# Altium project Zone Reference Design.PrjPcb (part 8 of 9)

## Sheet AM263P OSPI Bootmode.SchDoc
size 431 x 279 mm; Date: Not shown in title block; ApprovedBy: Not shown in title block; CheckedBy: Not shown in title block; Author: Not shown in title block; CompanyName: Not shown in title block; Engineer: Not shown in title block; Organization: Not shown in title block; Address1: Not shown in title block; Address2: Not shown in title block; Address3: Not shown in title block; Address4: Not shown in title block; DocumentNumber: 2; Revision: Use project parameter SCH_Rev; SheetNumber: 9; SheetTotal: 30; PageSetup: Record=PageOptions¦CenterHorizontal=True¦CenterVertical=True¦PrintScale=1.00¦XCorrection=1.00¦YCorrection=1.00¦PrintKind=0¦BorderSize=5000000¦LeftOffset=0¦BottomOffset=0¦Orientation=2¦PaperLength=1000¦PaperWidth=1000¦Scale=100¦PaperSource=15¦PrintQuality=600¦MediaType=1¦DitherType=10¦PaperKind=Letter¦PrintScaleMode=1
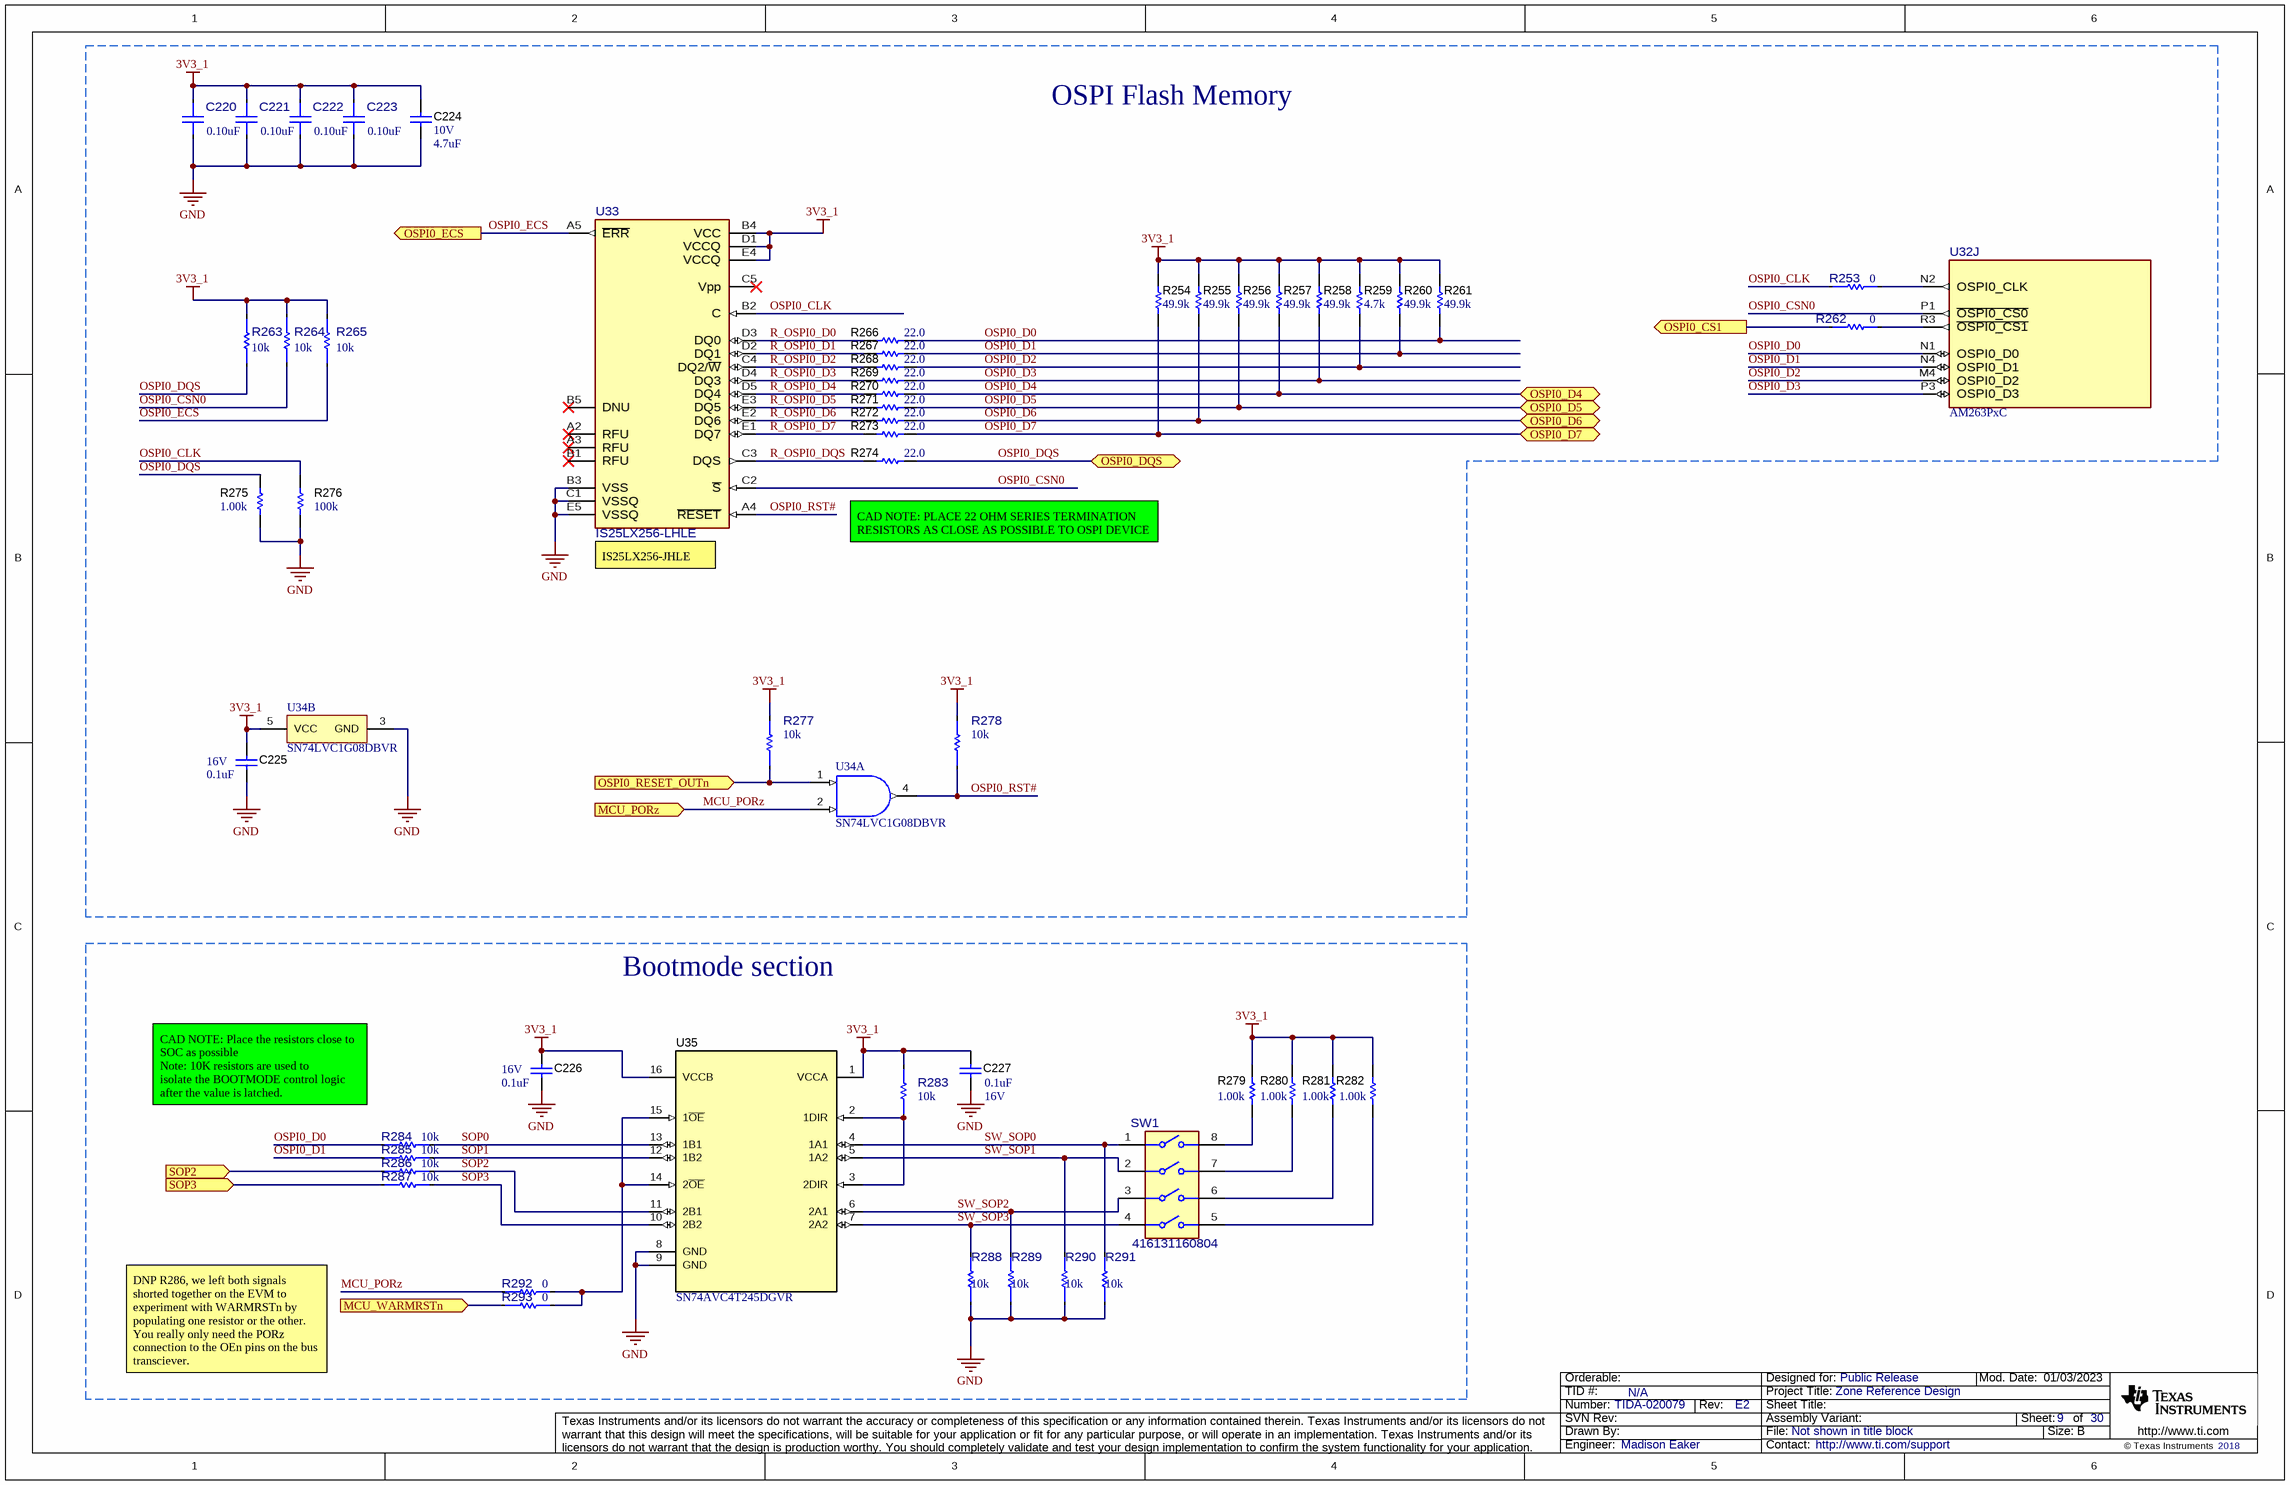
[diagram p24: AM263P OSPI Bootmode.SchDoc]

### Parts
C220  ValueDisplayed: 0.10uF  [FP-GRM155R71H104KE14D_0402-MFG]  (hidden comment: GRM155R71H104KE14D)
C221  ValueDisplayed: 0.10uF  [FP-GRM155R71H104KE14D_0402-MFG]  (hidden comment: GRM155R71H104KE14D)
C222  ValueDisplayed: 0.10uF  [FP-GRM155R71H104KE14D_0402-MFG]  (hidden comment: GRM155R71H104KE14D)
C223  ValueDisplayed: 0.10uF  [FP-GRM155R71H104KE14D_0402-MFG]  (hidden comment: GRM155R71H104KE14D)
C224  VDC_V: 10V  ValueDisplayed: 4.7uF  [0402]  (hidden comment: GRM155R61A475MEAAD)
C225  VDC_V: 16V  ValueDisplayed: 0.1uF  [0201]  (hidden comment: GRM033Z71C104KE14D)
C226  VDC_V: 16V  ValueDisplayed: 0.1uF  [0201]  (hidden comment: GRM033Z71C104KE14D)
C227  VDC_V: 16V  ValueDisplayed: 0.1uF  [0201]  (hidden comment: GRM033Z71C104KE14D)
R253  value 0  [FP-ERJ-2GE0R00X_0402-MFG]  (hidden comment: ERJ-2GE0R00X)
R254  ValueDisplayed: 49.9k  [0201]  (hidden comment: RC0201FR-0749K9L)
R255  ValueDisplayed: 49.9k  [0201]  (hidden comment: RC0201FR-0749K9L)
R256  ValueDisplayed: 49.9k  [0201]  (hidden comment: RC0201FR-0749K9L)
R257  ValueDisplayed: 49.9k  [0201]  (hidden comment: RC0201FR-0749K9L)
R258  ValueDisplayed: 49.9k  [0201]  (hidden comment: RC0201FR-0749K9L)
R259  ValueDisplayed: 4.7k  [0402]  (hidden comment: CRCW04024K70JNED)
R260  ValueDisplayed: 49.9k  [0201]  (hidden comment: RC0201FR-0749K9L)
R261  ValueDisplayed: 49.9k  [0201]  (hidden comment: RC0201FR-0749K9L)
R262  value 0  [FP-ERJ-2GE0R00X_0402-MFG]  (hidden comment: ERJ-2GE0R00X)
R263  value 10k  [FP-RC0402JR-0710KL_0402-MFG]  (hidden comment: RC0402JR-0710KL)
R264  value 10k  [FP-RC0402JR-0710KL_0402-MFG]  (hidden comment: RC0402JR-0710KL)
R265  value 10k  [FP-RC0402JR-0710KL_0402-MFG]  (hidden comment: RC0402JR-0710KL)
R266  ValueDisplayed: 22.0  [0201]  (hidden comment: RC0201FR-0722RL)
R267  ValueDisplayed: 22.0  [0201]  (hidden comment: RC0201FR-0722RL)
R268  ValueDisplayed: 22.0  [0201]  (hidden comment: RC0201FR-0722RL)
R269  ValueDisplayed: 22.0  [0201]  (hidden comment: RC0201FR-0722RL)
R270  ValueDisplayed: 22.0  [0201]  (hidden comment: RC0201FR-0722RL)
R271  ValueDisplayed: 22.0  [0201]  (hidden comment: RC0201FR-0722RL)
R272  ValueDisplayed: 22.0  [0201]  (hidden comment: RC0201FR-0722RL)
R273  ValueDisplayed: 22.0  [0201]  (hidden comment: RC0201FR-0722RL)
R274  ValueDisplayed: 22.0  [0201]  (hidden comment: RC0201FR-0722RL)
R275  ValueDisplayed: 1.00k  [0402]  (hidden comment: ERJ-2RKF1001X)
R276  ValueDisplayed: 100k  [0402]  (hidden comment: CRCW0402100KJNED)
R277  value 10k  [FP-RC0402JR-0710KL_0402-MFG]  (hidden comment: RC0402JR-0710KL)
R278  value 10k  [FP-RC0402JR-0710KL_0402-MFG]  (hidden comment: RC0402JR-0710KL)
R279  ValueDisplayed: 1.00k  [0402]  (hidden comment: ERJ-2RKF1001X)
R280  ValueDisplayed: 1.00k  [0402]  (hidden comment: ERJ-2RKF1001X)
R281  ValueDisplayed: 1.00k  [0402]  (hidden comment: ERJ-2RKF1001X)
R282  ValueDisplayed: 1.00k  [0402]  (hidden comment: ERJ-2RKF1001X)
R283  value 10k  [FP-RC0402JR-0710KL_0402-MFG]  (hidden comment: RC0402JR-0710KL)
R284  value 10k  [FP-RC0402JR-0710KL_0402-MFG]  (hidden comment: RC0402JR-0710KL)
R285  value 10k  [FP-RC0402JR-0710KL_0402-MFG]  (hidden comment: RC0402JR-0710KL)
R286  value 10k  [FP-RC0402JR-0710KL_0402-MFG]  (hidden comment: RC0402JR-0710KL)
R287  value 10k  [FP-RC0402JR-0710KL_0402-MFG]  (hidden comment: RC0402JR-0710KL)
R288  value 10k  [FP-RC0402JR-0710KL_0402-MFG]  (hidden comment: RC0402JR-0710KL)
R289  value 10k  [FP-RC0402JR-0710KL_0402-MFG]  (hidden comment: RC0402JR-0710KL)
R290  value 10k  [FP-RC0402JR-0710KL_0402-MFG]  (hidden comment: RC0402JR-0710KL)
R291  value 10k  [FP-RC0402JR-0710KL_0402-MFG]  (hidden comment: RC0402JR-0710KL)
R292  value 0  [FP-ERJ-2GE0R00X_0402-MFG]  (hidden comment: ERJ-2GE0R00X)
R293  value 0  [FP-ERJ-2GE0R00X_0402-MFG]  (hidden comment: ERJ-2GE0R00X)
SW1  416131160804  [FP-416131160804_SMT_SW-MFG]
U32  AM263PxC  [ZCZ0324A-MFG]  (part J of 13)
U33  IS25LX256-LHLE  [FP-IS25LX256-LHLE_TFBGA24-IPC_C]
U34  SN74LVC1G08DBVR  [DBV0005A_N]  (parts A,B of 2)
U35  SN74AVC4T245DGVR  [DGV0016A_N]

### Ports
MCU_PORz (in), MCU_WARMRSTn (in), OSPI0_CS1 (out), OSPI0_D4 (bidir), OSPI0_D5 (bidir), OSPI0_D6 (bidir), OSPI0_D7 (bidir), OSPI0_DQS (bidir), OSPI0_ECS (out), OSPI0_RESET_OUTn (in), SOP2 (in), SOP3 (in)

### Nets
3V3_1: C220.1 C221.1 C222.1 C223.1 C224.2 C225.1 C226.1 C227.1 R254.2 R255.2 R256.2 R257.2 R258.2 R259.2 R260.2 R261.2 R263.2 R264.1 R265.2 R277.2 R278.2 R279.2 R280.2 R281.2 R282.2 R283.2 U33.B4(VCC) U33.D1(VCCQ) U33.E4(VCCQ) U34.5(VCC) U35.1(VCCA) U35.16(VCCB)
GND: C220.2 C221.2 C222.2 C223.2 C224.1 C225.2 C226.2 C227.2 R275.1 R276.1 R288.1 R289.1 R290.1 R291.1 U33.B3(VSS) U33.C1(VSSQ) U33.E5(VSSQ) U34.3(GND) U35.8(GND) U35.9(GND)
MCU_PORz: R292.1 U34.2(B) ; port MCU_PORz
MCU_WARMRSTn: R293.1 ; port MCU_WARMRSTn
OSPI0_CLK: R253.1 R276.2 U33.B2(C)  [project net OSPI0_CLK_9]
OSPI0_CSN0: R264.2 U32.P1(~{OSPI0_CS0}) U33.C2(~{S})  [project net OSPI0_CSN0_9]
OSPI0_D0: R261.1 R266.2 R284.1 U32.N1(OSPI0_D0)  [project net OSPI0_D0_9]
OSPI0_D1: R260.1 R267.2 R285.1 U32.N4(OSPI0_D1)  [project net OSPI0_D1_9]
OSPI0_D2: R259.1 R268.2 U32.M4(OSPI0_D2)  [project net OSPI0_D2_9]
OSPI0_D3: R258.1 R269.2 U32.P3(OSPI0_D3)  [project net OSPI0_D3_9]
OSPI0_D4: R257.1 R270.2 ; port OSPI0_D4
OSPI0_D5: R256.1 R271.2 ; port OSPI0_D5
OSPI0_D6: R255.1 R272.2 ; port OSPI0_D6
OSPI0_D7: R254.1 R273.2 ; port OSPI0_D7
OSPI0_DQS: R263.1 R274.2 R275.2 ; port OSPI0_DQS
OSPI0_ECS: R265.1 U33.A5(~{ERR}) ; port OSPI0_ECS
OSPI0_RESET_OUTn: R277.1 U34.1(A) ; port OSPI0_RESET_OUTn
OSPI0_RST#: R278.1 U33.A4(~{RESET}) U34.4(Y)  [project net OSPI0_RST#_9]
R_OSPI0_D0: R266.1 U33.D3(DQ0)  [project net R_OSPI0_D0_9]
R_OSPI0_D1: R267.1 U33.D2(DQ1)  [project net R_OSPI0_D1_9]
R_OSPI0_D2: R268.1 U33.C4(DQ2/~{W})  [project net R_OSPI0_D2_9]
R_OSPI0_D3: R269.1 U33.D4(DQ3)  [project net R_OSPI0_D3_9]
R_OSPI0_D4: R270.1 U33.D5(DQ4)  [project net R_OSPI0_D4_9]
R_OSPI0_D5: R271.1 U33.E3(DQ5)  [project net R_OSPI0_D5_9]
R_OSPI0_D6: R272.1 U33.E2(DQ6)  [project net R_OSPI0_D6_9]
R_OSPI0_D7: R273.1 U33.E1(DQ7)  [project net R_OSPI0_D7_9]
R_OSPI0_DQS: R274.1 U33.C3(DQS)  [project net R_OSPI0_DQS_9]
SOP0: R284.2 U35.13(1B1)  [project net SOP0_9]
SOP1: R285.2 U35.12(1B2)  [project net SOP1_9]
SOP2: R286.2 U35.11(2B1)  [project net SOP2_9]
SOP3: R287.2 U35.10(2B2)  [project net SOP3_9]
SPI0_CLK: R286.1 ; port SOP2
SPI0_D0: R287.1 ; port SOP3
SPI7_CS2: R262.1 ; port OSPI0_CS1
SW_SOP0: R291.2 SW1.1 U35.4(1A1)  [project net SW_SOP0_9]
SW_SOP1: R290.2 SW1.2 U35.5(1A2)  [project net SW_SOP1_9]
SW_SOP2: R289.2 SW1.3 U35.6(2A1)  [project net SW_SOP2_9]
SW_SOP3: R288.2 SW1.4 U35.7(2A2)  [project net SW_SOP3_9]
NetR253_2: R253.2 U32.N2(OSPI0_CLK)
NetR262_2: R262.2 U32.R3(~{OSPI0_CS1})
NetR279_1: R279.1 SW1.8
NetR280_1: R280.1 SW1.7
NetR281_1: R281.1 SW1.6
NetR282_1: R282.1 SW1.5
NetR283_1: R283.1 U35.2(1DIR) U35.3(2DIR)
NetR292_2: R292.2 R293.2 U35.14(2~{OE}) U35.15(1~{OE})

Not connected (* = marked no-connect by the designer): U33 A2(RFU)* A3(RFU)* B1(RFU)* B5(DNU)* C5(Vpp)*

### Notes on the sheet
- OSPI Flash Memory
- (near U33) IS25LX256-JHLE
- (near R274) CAD NOTE: PLACE 22 OHM SERIES TERMINATION RESISTORS AS CLOSE AS POSSIBLE TO OSPI DEVICE
- Bootmode section
- CAD NOTE: Place the resistors close to SOC as possible
  Note: 10K resistors are used to
  isolate the BOOTMODE control logic
  after the value is latched.
- DNP R286, we left both signals shorted together on the EVM to experiment with WARMRSTn by populating one resistor or the other. You really only need the PORz connection to the OEn pins on the bus transciever.

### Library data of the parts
C220-C223 = CMP-0096855-1: Chip Multilayer Ceramic Capacitors for General Purpose, 0402, 0.10uF, X7R, 15%, 10%, 50V; Manufacturer: Murata; SizeZ_mm: 0.55mm; Value: 100nF; AEC Qualified: No
C224 = CMP-0006582-2: CAP, CERM, 4.7 uF, 10 V, +/- 20%, X5R, 0402; Manufacturer: MuRata; TaMin_C: -55°C; Polarized: N; SizeAreaWB_mm2: 3; Value1: Unknown; U/M: EA; Value: 4.7uF; TaMax_C: 85°C; SizeZ_mm: 0.6; SizeX_mm: 1; SizeY_mm: 0.5; Cap_F: 4.7µF; AEC Category: Q200
C225-C227 = CMP-0064970-1: CAP, CERM, 0.1 uF, 16 V,+/- 10%, X7R, 0201; Manufacturer: MuRata; TaMin_C: -55°C; Polarized: N; SizeAreaWB_mm2: 2.08; Value1: Unknown; U/M: EA; Value: 0.1uF; TaMax_C: 125°C; SizeZ_mm: 0.26; SizeX_mm: 0.6; SizeY_mm: 0.3; SizeArea_mm2: 0.18; Cap_F: 100nF; AEC Category: Q200
R253 R262 R292 R293 = CMP-0002710-1: 0 Ohms Jumper Chip Resistor 0402 (1005 Metric) Automotive AEC-Q200 Thick Film; Manufacturer: Panasonic; AEC Grade: Grade 0; AEC Qualified: Yes; SizeZ_mm: 0.4mm; Power: 100mW
R254-R258 R260 R261 = CMP-0027732-1: RES, 49.9 k, 1%, 0.05 W, 0201; Manufacturer: Yageo America; Power_W: 50mW; TempCo: 200 ppm/C; Value_Code: 49k9; U/M: EA; Value: 49.9k; EIA_Code: E96; SizeX_mm: 0.6; SizeY_mm: 0.3; SizeZ_mm: 0.26; Value2: 0.05W; SizeArea_mm2: 0.18; AEC Qualified: N; VDC_V: 25V; AEC Category: Q200
R259 = CMP-0026938-5: RES, 4.7 k, 5%, 0.063 W, AEC-Q200 Grade 0, 0402; Manufacturer: Vishay-Dale; Power_W: 63mW; TempCo: 200 ppm/C; Value_Code: 4k70; Value: 4.7k; EIA_Code: E24; SizeX_mm: 1; SizeY_mm: 0.5; SizeZ_mm: 0.6; Value2: 0.063W; AEC Qualified: Y; VDC_V: 50V; AEC Category: Q200; AEC Grade: 0
R263-R265 R277 R278 R283-R291 = CMP-0094798-1: Res Thick Film 0402 10K Ohm 5% 0.063W(1/16W) ±100ppm/C Pad SMD T/R; Manufacturer: YAGEO; Power_W: 63mW; TempCo: 100ppm/°C; SizeZ_mm: 0.4mm; AEC Qualified: No; VDC_V: 50V; Category Cd01000Bfc2916C6: Single Components; Category 5C6A91606D4187Ad: Resistors; Category 7542B8484461Ae85: Passive Components
R266-R274 = CMP-0027500-1: RES, 22.0, 1%, 0.05 W, 0201; Manufacturer: Yageo America; Power_W: 50mW; TempCo: 200 ppm/C; Value_Code: 22R0; U/M: EA; Value: 22.0; Res_ohm: 22; SizeX_mm: 0.6; SizeY_mm: 0.3; SizeZ_mm: 0.26; Value2: 0.05W; SizeArea_mm2: 0.18; AEC Qualified: N; VDC_V: 25V; AEC Category: Q200
R275 R279-R282 = CMP-0026657-1: RES, 1.00 k, 1%, 0.1 W, 0402; Manufacturer: Panasonic; Value_Code: 1k00; SizeArea_mm2: 0.5; AEC Category: Q200; Res_ohm: 1k; Value: 1.00k; SizeZ_mm: 0.6; EIA_Code: E96; TempCo: 100 ppm/C; Power_W: 100mW; VDC_V: 50V; Value2: 0.1W; U/M: EA; SizeX_mm: 1
R276 = CMP-0026823-3: RES, 100 k, 5%, 0.063 W, AEC-Q200 Grade 0, 0402; Manufacturer: Vishay-Dale; Value2: 0.063W; EIA_Code: E24; Value: 100k; SizeArea_mm2: 0.5; TempCo: 200 ppm/C; SizeZ_mm: 0.6; AEC Category: Q200; VDC_V: 50V; Power_W: 63mW; AEC Grade: 0; SizeX_mm: 1; AEC Qualified: Y
SW1 = CMP-0093176-1: Dip Switch SPST 4 Position Surface Mount Slide (Standard) Actuator 25mA 24VDC; Manufacturer: Wurth; PositionCount: 4; Electromechanical Life: 1000Cycles; Circuit: 4PST; Coil Resistance_ohm: 100mΩ; VDC_V: 24V; Standoff Height: 0mm; SizeZ_mm: 2.65mm; AEC Qualified: No
U32 = CMP-0001698-2: Sitara™ Microcontroller; Manufacturer: Texas Instruments; SizeZ_mm: 1.4mm; Core Architecture: ARM Cortex-R5F; Data Bus Width: 32bits; Frequency_Fixed: 200MHz; Interface: I2C,SPI,UART,CAN,LIN,Ethernet,Other; Max Supply Voltage: 3.465V; Memory Size: 2MBytes; Memory Type: RAM; Min Supply Voltage: 1.14V; Number Of Cores: 1; Number Of I/Os: 140; Number Of I2C Channels: 4; Number Of Spi Channels: 5; Number Of Uart Channels: 6; Standoff Height: 0.35mm; AEC Category: Q200; CompType: IC
U33 = CMP-0120691-1: FLASH Memory IC 256Mbit SPI - Octal I/O 133 MHz 6 ns 24-TFBGA (6x8); Manufacturer: ISSI; SizeZ_mm: 1.2mm; Access Time: 6ns; AEC Qualified: No; Frequency_Fixed: 133MHz; Max Supply Voltage: 3.6V; Min Supply Voltage: 2.7V; Nominal Supply Current: 0.13-48mA; Standoff Height: 0.26mm; TaMax_C: +105°C; TaMin_C: -40°C
U34 = CMP-0051588-2: Single 2-Input Positive-AND Gate, DBV0005A, LARGE T&R; Manufacturer: Texas Instruments; Logic: True; ICC @ Nom Voltage(Max)(mA): 0.01; VCC(Min)(V): 1.65; Bits(#): 1; Rating: Catalog; Schmitt Trigger: No; Voltage(Nom)(V): 1.8,2.5,3.3,5; Output Drive (IOL/IOH)(Max)(mA): 32/-32; Gate Type: AND; tpd @ Nom Voltage(Max)(ns): 4.5,6,4,5; VCC(Max)(V): 5.5; Output Type: CMOS; F @ Nom Voltage(Max)(Mhz): 150; Input Type: CMOS/TTL; Technology Family: LVC; AEC Category: Q200; AEC Qualified: N; CompType: IC
U35 = CMP-0066446-2: 4-Bit Dual-Supply Bus Transceiver with Configurable Voltage-Level Shifting and 3-State Outputs, DGV0016A (TVSOP-16); Alternate Manufacturer: Texas Instruments; Green_Lifecycle: Active; SizeAreaWB_mm2: 70.56; Green_REACh: Passed; SizeZ_mm: 1.2; SizeX_mm: 6.4; SizeArea_mm2: 40.96; CompType: IC; AEC Category: Q200; AEC Qualified: N

## Sheet AM263P ADC.SchDoc
size 431 x 279 mm; Date: Not shown in title block; ApprovedBy: Not shown in title block; CheckedBy: Not shown in title block; Author: Not shown in title block; CompanyName: Not shown in title block; Engineer: Not shown in title block; Organization: Not shown in title block; Address1: Not shown in title block; Address2: Not shown in title block; Address3: Not shown in title block; Address4: Not shown in title block; DocumentNumber: 2; Revision: Use project parameter SCH_Rev; SheetNumber: 10; SheetTotal: 30; PageSetup: Record=PageOptions¦CenterHorizontal=True¦CenterVertical=True¦PrintScale=1.00¦XCorrection=1.00¦YCorrection=1.00¦PrintKind=0¦BorderSize=5000000¦LeftOffset=0¦BottomOffset=0¦Orientation=2¦PaperLength=1000¦PaperWidth=1000¦Scale=100¦PaperSource=15¦PrintQuality=600¦MediaType=1¦DitherType=10¦PaperKind=Letter¦PrintScaleMode=1
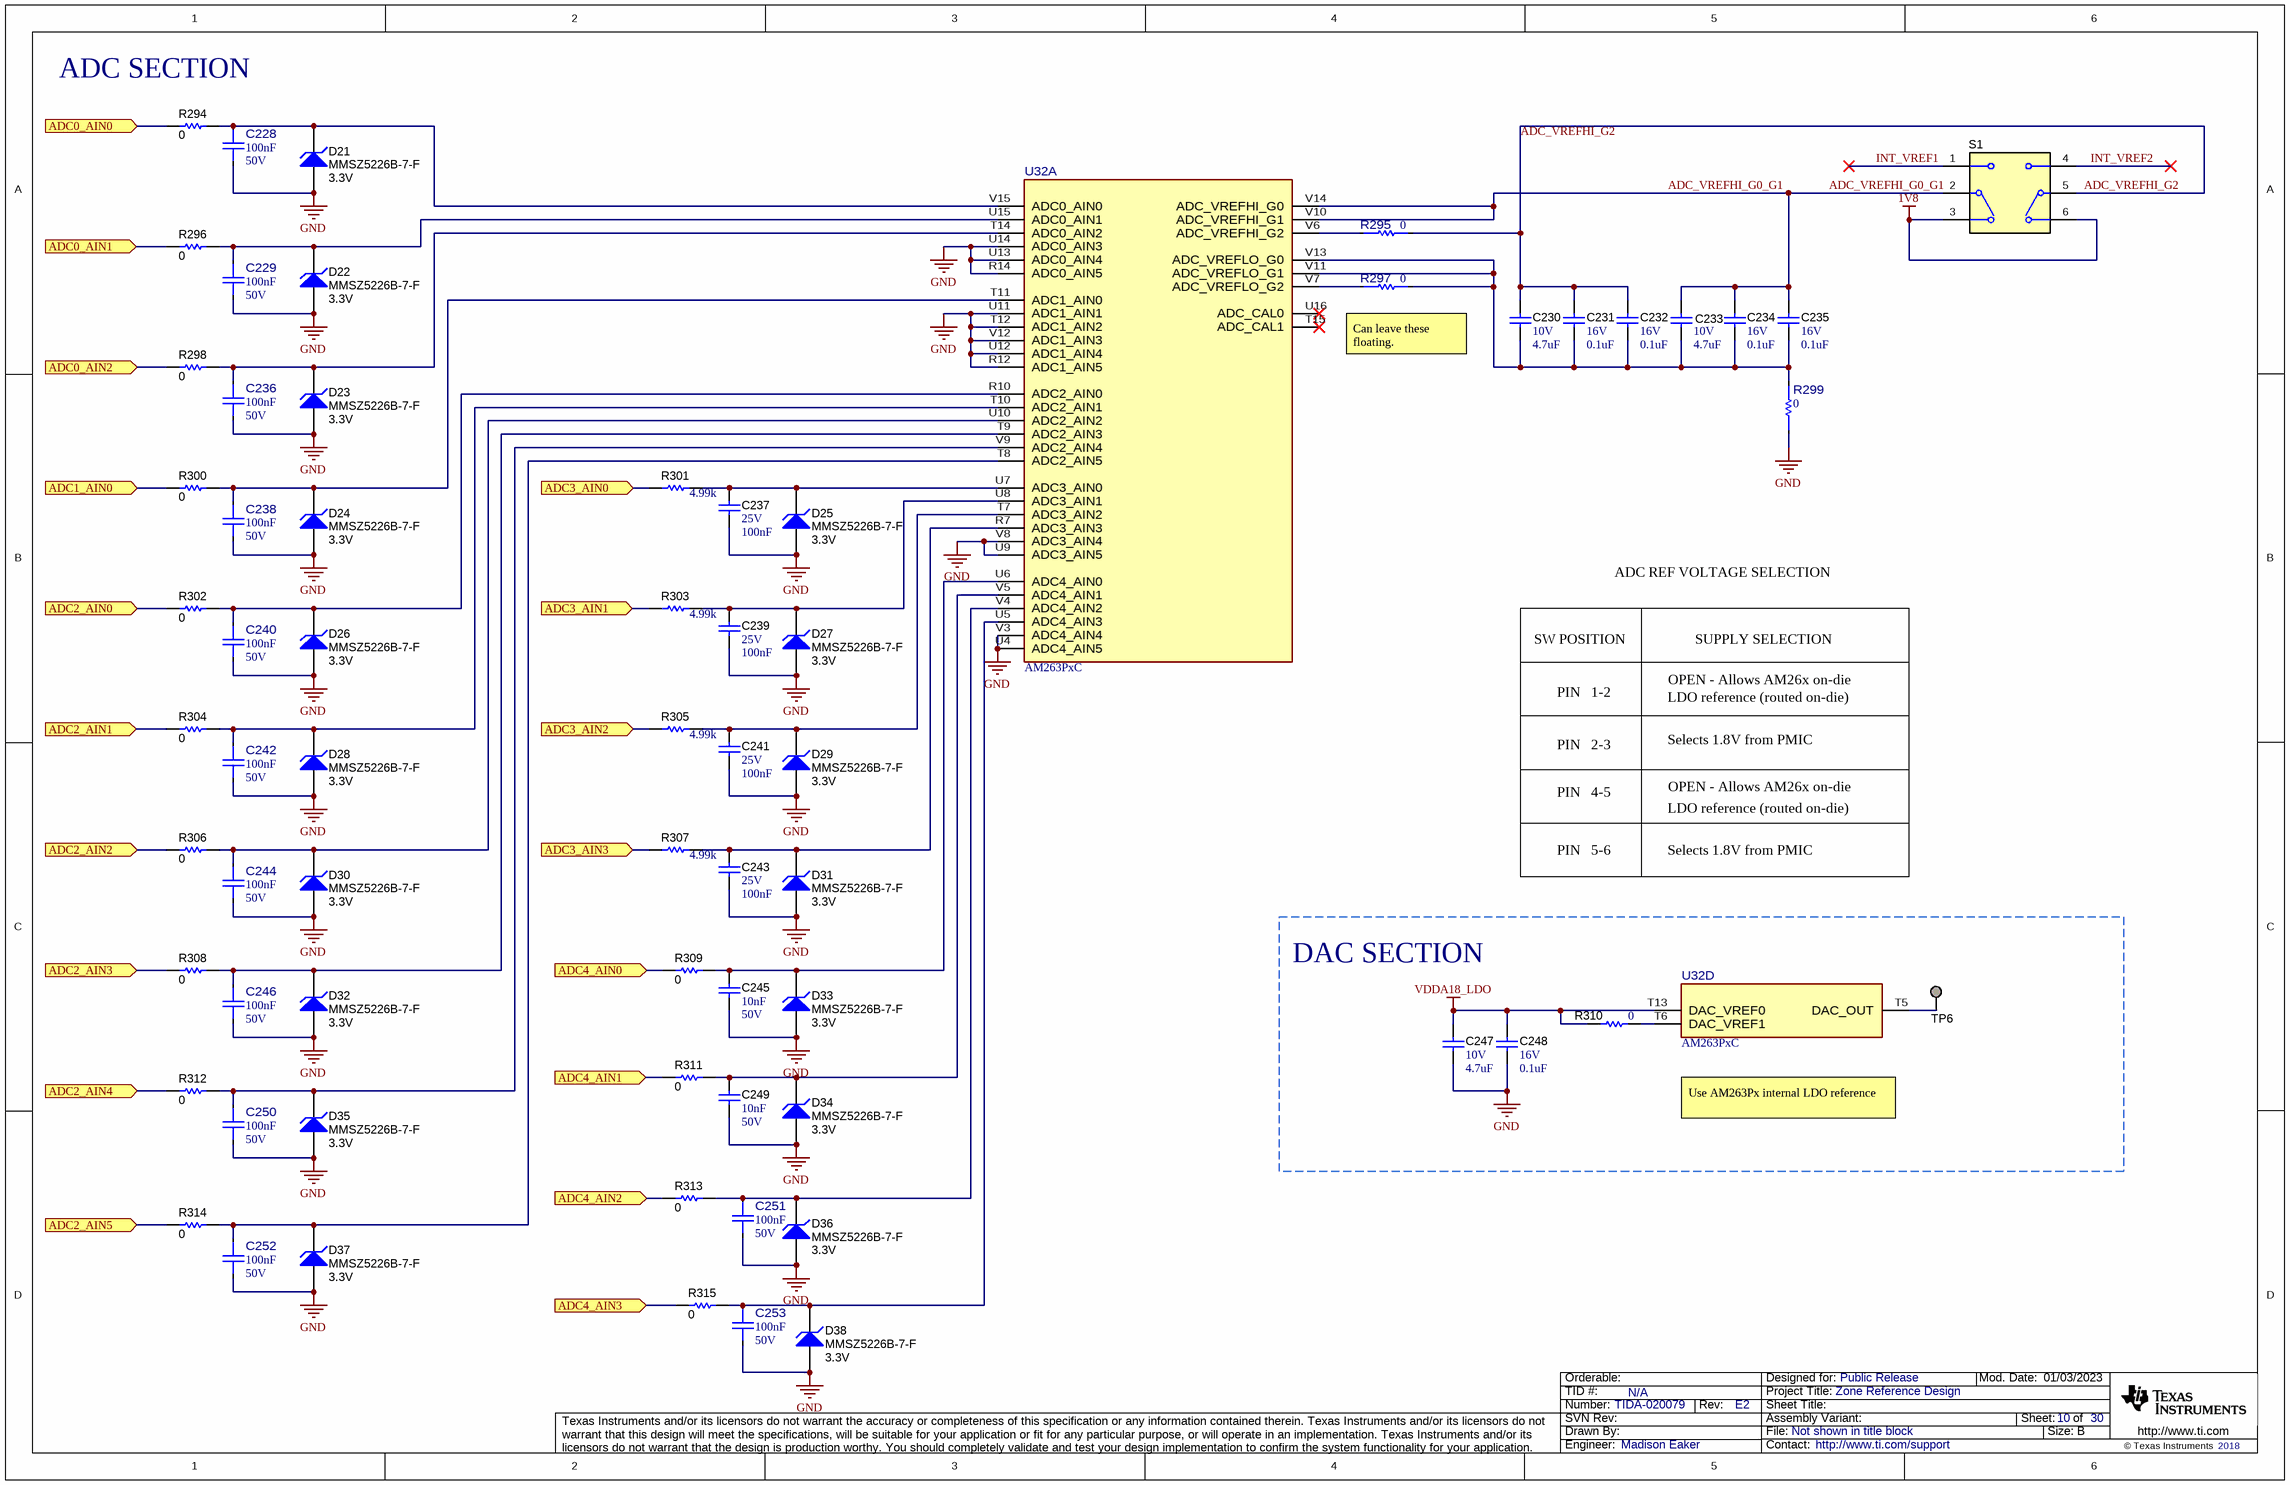
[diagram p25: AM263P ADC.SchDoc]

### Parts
C228  Cap_F: 100nF  VDC_V: 50V  [FP-C0603C104J5RAC7867_0603-MFG]  (hidden comment: C0603C104J5RAC7867)
C229  Cap_F: 100nF  VDC_V: 50V  [FP-C0603C104J5RAC7867_0603-MFG]  (hidden comment: C0603C104J5RAC7867)
C230  VDC_V: 10V  ValueDisplayed: 4.7uF  [0402]  (hidden comment: GRM155R61A475MEAAD)
C231  VDC_V: 16V  ValueDisplayed: 0.1uF  [0201]  (hidden comment: GRM033Z71C104KE14D)
C232  VDC_V: 16V  ValueDisplayed: 0.1uF  [0201]  (hidden comment: GRM033Z71C104KE14D)
C233  VDC_V: 10V  ValueDisplayed: 4.7uF  [0402]  (hidden comment: GRM155R61A475MEAAD)
C234  VDC_V: 16V  ValueDisplayed: 0.1uF  [0201]  (hidden comment: GRM033Z71C104KE14D)
C235  VDC_V: 16V  ValueDisplayed: 0.1uF  [0201]  (hidden comment: GRM033Z71C104KE14D)
C236  Cap_F: 100nF  VDC_V: 50V  [FP-C0603C104J5RAC7867_0603-MFG]  (hidden comment: C0603C104J5RAC7867)
C237  VDC_V: 25V  Cap_F: 100nF  [0603]  (hidden comment: GCM188R71E104KA57D)
C238  Cap_F: 100nF  VDC_V: 50V  [FP-C0603C104J5RAC7867_0603-MFG]  (hidden comment: C0603C104J5RAC7867)
C239  VDC_V: 25V  Cap_F: 100nF  [0603]  (hidden comment: GCM188R71E104KA57D)
C240  Cap_F: 100nF  VDC_V: 50V  [FP-C0603C104J5RAC7867_0603-MFG]  (hidden comment: C0603C104J5RAC7867)
C241  VDC_V: 25V  Cap_F: 100nF  [0603]  (hidden comment: GCM188R71E104KA57D)
C242  Cap_F: 100nF  VDC_V: 50V  [FP-C0603C104J5RAC7867_0603-MFG]  (hidden comment: C0603C104J5RAC7867)
C243  VDC_V: 25V  Cap_F: 100nF  [0603]  (hidden comment: GCM188R71E104KA57D)
C244  Cap_F: 100nF  VDC_V: 50V  [FP-C0603C104J5RAC7867_0603-MFG]  (hidden comment: C0603C104J5RAC7867)
C245  Cap_F: 10nF  VDC_V: 50V  [0603]  (hidden comment: C0603C103J5RACTU)
C246  Cap_F: 100nF  VDC_V: 50V  [FP-C0603C104J5RAC7867_0603-MFG]  (hidden comment: C0603C104J5RAC7867)
C247  VDC_V: 10V  ValueDisplayed: 4.7uF  [0402]  (hidden comment: GRM155R61A475MEAAD)
C248  VDC_V: 16V  ValueDisplayed: 0.1uF  [0201]  (hidden comment: GRM033Z71C104KE14D)
C249  Cap_F: 10nF  VDC_V: 50V  [0603]  (hidden comment: C0603C103J5RACTU)
C250  Cap_F: 100nF  VDC_V: 50V  [FP-C0603C104J5RAC7867_0603-MFG]  (hidden comment: C0603C104J5RAC7867)
C251  Cap_F: 100nF  VDC_V: 50V  [FP-C0603C104J5RAC7867_0603-MFG]  (hidden comment: C0603C104J5RAC7867)
C252  Cap_F: 100nF  VDC_V: 50V  [FP-C0603C104J5RAC7867_0603-MFG]  (hidden comment: C0603C104J5RAC7867)
C253  Cap_F: 100nF  VDC_V: 50V  [FP-C0603C104J5RAC7867_0603-MFG]  (hidden comment: C0603C104J5RAC7867)
D21  MMSZ5226B-7-F  value 3.3V  [SOD-123]
D22  MMSZ5226B-7-F  value 3.3V  [SOD-123]
D23  MMSZ5226B-7-F  value 3.3V  [SOD-123]
D24  MMSZ5226B-7-F  value 3.3V  [SOD-123]
D25  MMSZ5226B-7-F  value 3.3V  [SOD-123]
D26  MMSZ5226B-7-F  value 3.3V  [SOD-123]
D27  MMSZ5226B-7-F  value 3.3V  [SOD-123]
D28  MMSZ5226B-7-F  value 3.3V  [SOD-123]
D29  MMSZ5226B-7-F  value 3.3V  [SOD-123]
D30  MMSZ5226B-7-F  value 3.3V  [SOD-123]
D31  MMSZ5226B-7-F  value 3.3V  [SOD-123]
D32  MMSZ5226B-7-F  value 3.3V  [SOD-123]
D33  MMSZ5226B-7-F  value 3.3V  [SOD-123]
D34  MMSZ5226B-7-F  value 3.3V  [SOD-123]
D35  MMSZ5226B-7-F  value 3.3V  [SOD-123]
D36  MMSZ5226B-7-F  value 3.3V  [SOD-123]
D37  MMSZ5226B-7-F  value 3.3V  [SOD-123]
D38  MMSZ5226B-7-F  value 3.3V  [SOD-123]
R294  value 0  [0603L]  (hidden comment: Resistor)
R295  value 0  [FP-ERJ-2GE0R00X_0402-MFG]  (hidden comment: ERJ-2GE0R00X)
R296  value 0  [0603L]  (hidden comment: Resistor)
R297  value 0  [FP-ERJ-2GE0R00X_0402-MFG]  (hidden comment: ERJ-2GE0R00X)
R298  value 0  [0603L]  (hidden comment: Resistor)
R299  value 0  [FP-ERJ-2GE0R00X_0402-MFG]  (hidden comment: ERJ-2GE0R00X)
R300  value 0  [0603L]  (hidden comment: Resistor)
R301  ValueDisplayed: 4.99k  [0603]  (hidden comment: CRCW06034K99FKEA)
R302  value 0  [0603L]  (hidden comment: Resistor)
R303  ValueDisplayed: 4.99k  [0603]  (hidden comment: CRCW06034K99FKEA)
R304  value 0  [0603L]  (hidden comment: Resistor)
R305  ValueDisplayed: 4.99k  [0603]  (hidden comment: CRCW06034K99FKEA)
R306  value 0  [0603L]  (hidden comment: Resistor)
R307  ValueDisplayed: 4.99k  [0603]  (hidden comment: CRCW06034K99FKEA)
R308  value 0  [0603L]  (hidden comment: Resistor)
R309  value 0  [0603L]  (hidden comment: Resistor)
R310  ValueDisplayed: 0  [0201]  (hidden comment: ERJ-1GN0R00C)
R311  value 0  [0603L]  (hidden comment: Resistor)
R312  value 0  [0603L]  (hidden comment: Resistor)
R313  value 0  [0603L]  (hidden comment: Resistor)
R314  value 0  [0603L]  (hidden comment: Resistor)
R315  value 0  [0603L]  (hidden comment: Resistor)
S1  CAS-D20TA  [SW_CAS-D20TA]  (value not drawn)
TP6  TESTPOINT  [TP_25MIL-SMT]  (value not drawn)  (no BOM)
U32  AM263PxC  [ZCZ0324A-MFG]  (parts A,D of 13)

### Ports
ADC0_AIN0 (in), ADC0_AIN1 (in), ADC0_AIN2 (in), ADC1_AIN0 (in), ADC2_AIN0 (in), ADC2_AIN1 (in), ADC2_AIN2 (in), ADC2_AIN3 (in), ADC2_AIN4 (in), ADC2_AIN5 (in), ADC3_AIN0 (in), ADC3_AIN1 (in), ADC3_AIN2 (in), ADC3_AIN3 (in), ADC4_AIN0 (in), ADC4_AIN1 (in), ADC4_AIN2 (in), ADC4_AIN3 (in)

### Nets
1V8: S1.3 S1.6
GND: C228.2 C229.2 C236.2 C237.2 C238.2 C239.2 C240.2 C241.2 C242.2 C243.2 C244.2 C245.1 C246.2 C247.1 C248.1 C249.1 C250.2 C251.2 C252.2 C253.2 D21.2(A) D22.2(A) D23.2(A) D24.2(A) D25.2(A) D26.2(A) D27.2(A) D28.2(A) D29.2(A) D30.2(A) D31.2(A) D32.2(A) D33.2(A) D34.2(A) D35.2(A) D36.2(A) D37.2(A) D38.2(A) R299.1 U32.R12(ADC1_AIN5) U32.R14(ADC0_AIN5) U32.T12(ADC1_AIN2) U32.U4(ADC4_AIN5) U32.U9(ADC3_AIN5) U32.U11(ADC1_AIN1) U32.U12(ADC1_AIN4) U32.U13(ADC0_AIN4) U32.U14(ADC0_AIN3) U32.V3(ADC4_AIN4) U32.V8(ADC3_AIN4) U32.V12(ADC1_AIN3)
VDDA18_LDO: C247.2 C248.2 R310.1 U32.T13(DAC_VREF0)
3V3_AlwaysOn_Monitor_MCU: R298.1 ; port ADC0_AIN2
ADC0_AIN0: R294.1 ; port ADC0_AIN0
ADC0_AIN1: R296.1 ; port ADC0_AIN1
ADC1_AIN0: R300.1 ; port ADC1_AIN0
ADC2_AIN0: R302.1 ; port ADC2_AIN0
ADC2_AIN1: R304.1 ; port ADC2_AIN1
ADC2_AIN2: R306.1 ; port ADC2_AIN2
ADC2_AIN5: R314.1 ; port ADC2_AIN5
ADC3_AIN0: R301.1 ; port ADC3_AIN0
ADC3_AIN1: R303.1 ; port ADC3_AIN1
ADC3_AIN2: R305.1 ; port ADC3_AIN2
ADC3_AIN3: R307.1 ; port ADC3_AIN3
ADC4_AIN0: R309.1 ; port ADC4_AIN0
ADC4_AIN1: R311.1 ; port ADC4_AIN1
ADC4_AIN2: R313.1 ; port ADC4_AIN2
ADC4_AIN3: R315.1 ; port ADC4_AIN3
ADC_VREFHI_G0_G1: C233.2 C234.2 C235.2 S1.2(C) U32.V10(ADC_VREFHI_G1) U32.V14(ADC_VREFHI_G0)  [project net ADC_VREFHI_G0_G1_10]
ADC_VREFHI_G2: C230.2 C231.2 C232.2 R295.2 S1.5(C)  [project net ADC_VREFHI_G2_10]
IMON: R308.1 ; port ADC2_AIN3
INT_VREF1: S1.1  [project net INT_VREF1_10]
INT_VREF2: S1.4  [project net INT_VREF2_10]
ITMPO: R312.1 ; port ADC2_AIN4
NetC228_1: C228.1 D21.1(K) R294.2 U32.V15(ADC0_AIN0)
NetC229_1: C229.1 D22.1(K) R296.2 U32.U15(ADC0_AIN1)
NetC230_1: C230.1 C231.1 C232.1 C233.1 C234.1 C235.1 R297.2 R299.2 U32.V11(ADC_VREFLO_G1) U32.V13(ADC_VREFLO_G0)
NetC236_1: C236.1 D23.1(K) R298.2 U32.T14(ADC0_AIN2)
NetC237_1: C237.1 D25.1(K) R301.2 U32.U7(ADC3_AIN0)
NetC238_1: C238.1 D24.1(K) R300.2 U32.T11(ADC1_AIN0)
NetC239_1: C239.1 D27.1(K) R303.2 U32.U8(ADC3_AIN1)
NetC240_1: C240.1 D26.1(K) R302.2 U32.R10(ADC2_AIN0)
NetC241_1: C241.1 D29.1(K) R305.2 U32.T7(ADC3_AIN2)
NetC242_1: C242.1 D28.1(K) R304.2 U32.T10(ADC2_AIN1)
NetC243_1: C243.1 D31.1(K) R307.2 U32.R7(ADC3_AIN3)
NetC244_1: C244.1 D30.1(K) R306.2 U32.U10(ADC2_AIN2)
NetC245_2: C245.2 D33.1(K) R309.2 U32.U6(ADC4_AIN0)
NetC246_1: C246.1 D32.1(K) R308.2 U32.T9(ADC2_AIN3)
NetC249_2: C249.2 D34.1(K) R311.2 U32.V5(ADC4_AIN1)
NetC250_1: C250.1 D35.1(K) R312.2 U32.V9(ADC2_AIN4)
NetC251_1: C251.1 D36.1(K) R313.2 U32.V4(ADC4_AIN2)
NetC252_1: C252.1 D37.1(K) R314.2 U32.T8(ADC2_AIN5)
NetC253_1: C253.1 D38.1(K) R315.2 U32.U5(ADC4_AIN3)
NetR295_1: R295.1 U32.V6(ADC_VREFHI_G2)
NetR297_1: R297.1 U32.V7(ADC_VREFLO_G2)
NetR310_2: R310.2 U32.T6(DAC_VREF1)
NetTP6_1: TP6.1 U32.T5(DAC_OUT)

Not connected (* = marked no-connect by the designer): U32 T15(ADC_CAL1)* U16(ADC_CAL0)*

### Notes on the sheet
- ADC SECTION
- Type @ to refer to a designator or a net
- (near R297) Can leave these floating.
- ADC REF VOLTAGE SELECTION
- SW POSITION
- PIN   1-2
- LDO reference (routed on-die)
- OPEN - Allows AM26x on-die
- SUPPLY SELECTION
- PIN   2-3
- Selects 1.8V from PMIC
- PIN   4-5
- PIN   5-6
- DAC SECTION
- Use AM263Px internal LDO reference

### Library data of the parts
C228 C229 C236 C238 C240 C242 C244 C246 C250-C253 = CMP-0122528-1: Cap Ceramic 0.1uF 50V X7R 5% SMD 1.6 x 0.8 mm 125 C Paper T/R; Manufacturer: KEMET; AEC Qualified: No; SizeZ_mm: 0.95mm; TempCo: 15%; Value: 100nF
C230 C233 C247 = CMP-0006582-2: as C224 on sheet AM263P OSPI Bootmode
C231 C232 C234 C235 C248 = CMP-0064970-1: as C225-C227 on sheet AM263P OSPI Bootmode
C237 C239 C241 C243 = CMP-0084679-1: CAP, CERM, 0.1 µF, 25 V,+/- 10%, X7R, AEC-Q200 Grade 1, 0603; Manufacturer: MuRata; TaMin_C: -55°C; SizeY_mm: 0.8; Polarized: N; SizeArea_mm2: 1.28; SizeZ_mm: 1; SizeX_mm: 1.6; AEC Qualified: Y; AEC Category: Q200; Value: 0.1uF; ValueDisplayed: 0.1µF; TaMax_C: 125°C; U/M: EA; SizeAreaWB_mm2: 4.68
C245 C249 = CMP-0006850-2: CAP, CERM, 0.01 uF, 50 V, +/- 5%, X7R, 0603; Manufacturer: Kemet; TaMin_C: -55°C; Polarized: N; SizeAreaWB_mm2: 4.68; Value1: Unknown; U/M: EA; Value: 0.01uF; TaMax_C: 125°C; SizeZ_mm: 1; SizeX_mm: 1.6; SizeY_mm: 0.8; SizeArea_mm2: 1.28; AEC Category: Q200
D21-D38 = CMP-0005797-3: Diode, Zener, 3.3 V, 500 mW, SOD-123; Manufacturer: Diodes Inc.; SizeZ_mm: 1.35; SizeX_mm: 3.85; Value1: 0.5W; RJA_CperW: 350; SizeAreaWB_mm2: 13.095; Power_W: 500mW; SizeArea_mm2: 6.545; SizeY_mm: 1.7; AEC Category: Q101
R294 R296 R298 R300 R302 R304 R306 R308 R309 R311-R315 = CMP-0025697-4: RES, 0, 5%, 0.1 W, AEC-Q200 Grade 0, 0603; PartNumber: CRCW06030000Z0EA; Manufacturer: Vishay-Dale; Value_Code: 0000; Power_W: 100mW; Value2: 0.1W; VDC_V: 75V; TempCo: 200 ppm/C; EIA_Code: E24; AEC Category: Q200; AEC Qualified: Y; SizeArea_mm2: 1.28; SizeX_mm: 1.6; SizeY_mm: 0.8; SizeZ_mm: 1
R295 R297 R299 = CMP-0002710-1: as R253 on sheet AM263P OSPI Bootmode
R301 R303 R305 R307 = CMP-0022458-4: RES, 4.99 k, 1%, 0.1 W, AEC-Q200 Grade 0, 0603; Manufacturer: Vishay-Dale; Power_W: 100mW; TempCo: 100 ppm/C; Value_Code: 4k99; Value: 4.99k; EIA_Code: E96; SizeX_mm: 1.6; SizeY_mm: 0.8; SizeZ_mm: 1; Value2: 0.1W; SizeArea_mm2: 1.28; AEC Qualified: Y; VDC_V: 75V; AEC Category: Q200; AEC Grade: 0
R310 = CMP-0065361-1: RES, 0, 5%, .05 W, AEC-Q200 Grade 0, 0201; Manufacturer: Panasonic; Power_W: 50mW; Green_Lifecycle: Not Set; TempCo: ppm/C; Value_Code: 0000; Green_REACh: Incomplete; U/M: EA; Value: 0; EIA_Code: E24; SizeX_mm: 0.6; SizeY_mm: 0.3; SizeZ_mm: 0.26; Value2: .05W; SizeArea_mm2: 0.18; AEC Qualified: Y; AEC Category: Q200
S1 = CMP-0002233-1: Switch, Dual SPDT,  2 Pos, 0.1A, 6VDC, SMD; Manufacturer: Copal Electronics; CurrentRating_mA: 100A; SwitchFunction: On-On; VDC_V: 6V; PositionCount: 2
TP6 = CMP-0078143-3: TEST POINT.  No entry in BOM.
U32 = CMP-0001698-2: as U32 on sheet AM263P OSPI Bootmode

## Sheet AM263P PRU_EPWM.SchDoc
size 431 x 279 mm; Date: Not shown in title block; ApprovedBy: Not shown in title block; CheckedBy: Not shown in title block; Author: Not shown in title block; CompanyName: Not shown in title block; Engineer: Not shown in title block; Organization: Not shown in title block; Address1: Not shown in title block; Address2: Not shown in title block; Address3: Not shown in title block; Address4: Not shown in title block; DocumentNumber: 2; Revision: Use project parameter SCH_Rev; SheetNumber: 8; SheetTotal: 30; PageSetup: Record=PageOptions¦CenterHorizontal=True¦CenterVertical=True¦PrintScale=1.00¦XCorrection=1.00¦YCorrection=1.00¦PrintKind=0¦BorderSize=5000000¦LeftOffset=0¦BottomOffset=0¦Orientation=2¦PaperLength=1000¦PaperWidth=1000¦Scale=100¦PaperSource=15¦PrintQuality=600¦MediaType=1¦DitherType=10¦PaperKind=Letter¦PrintScaleMode=1
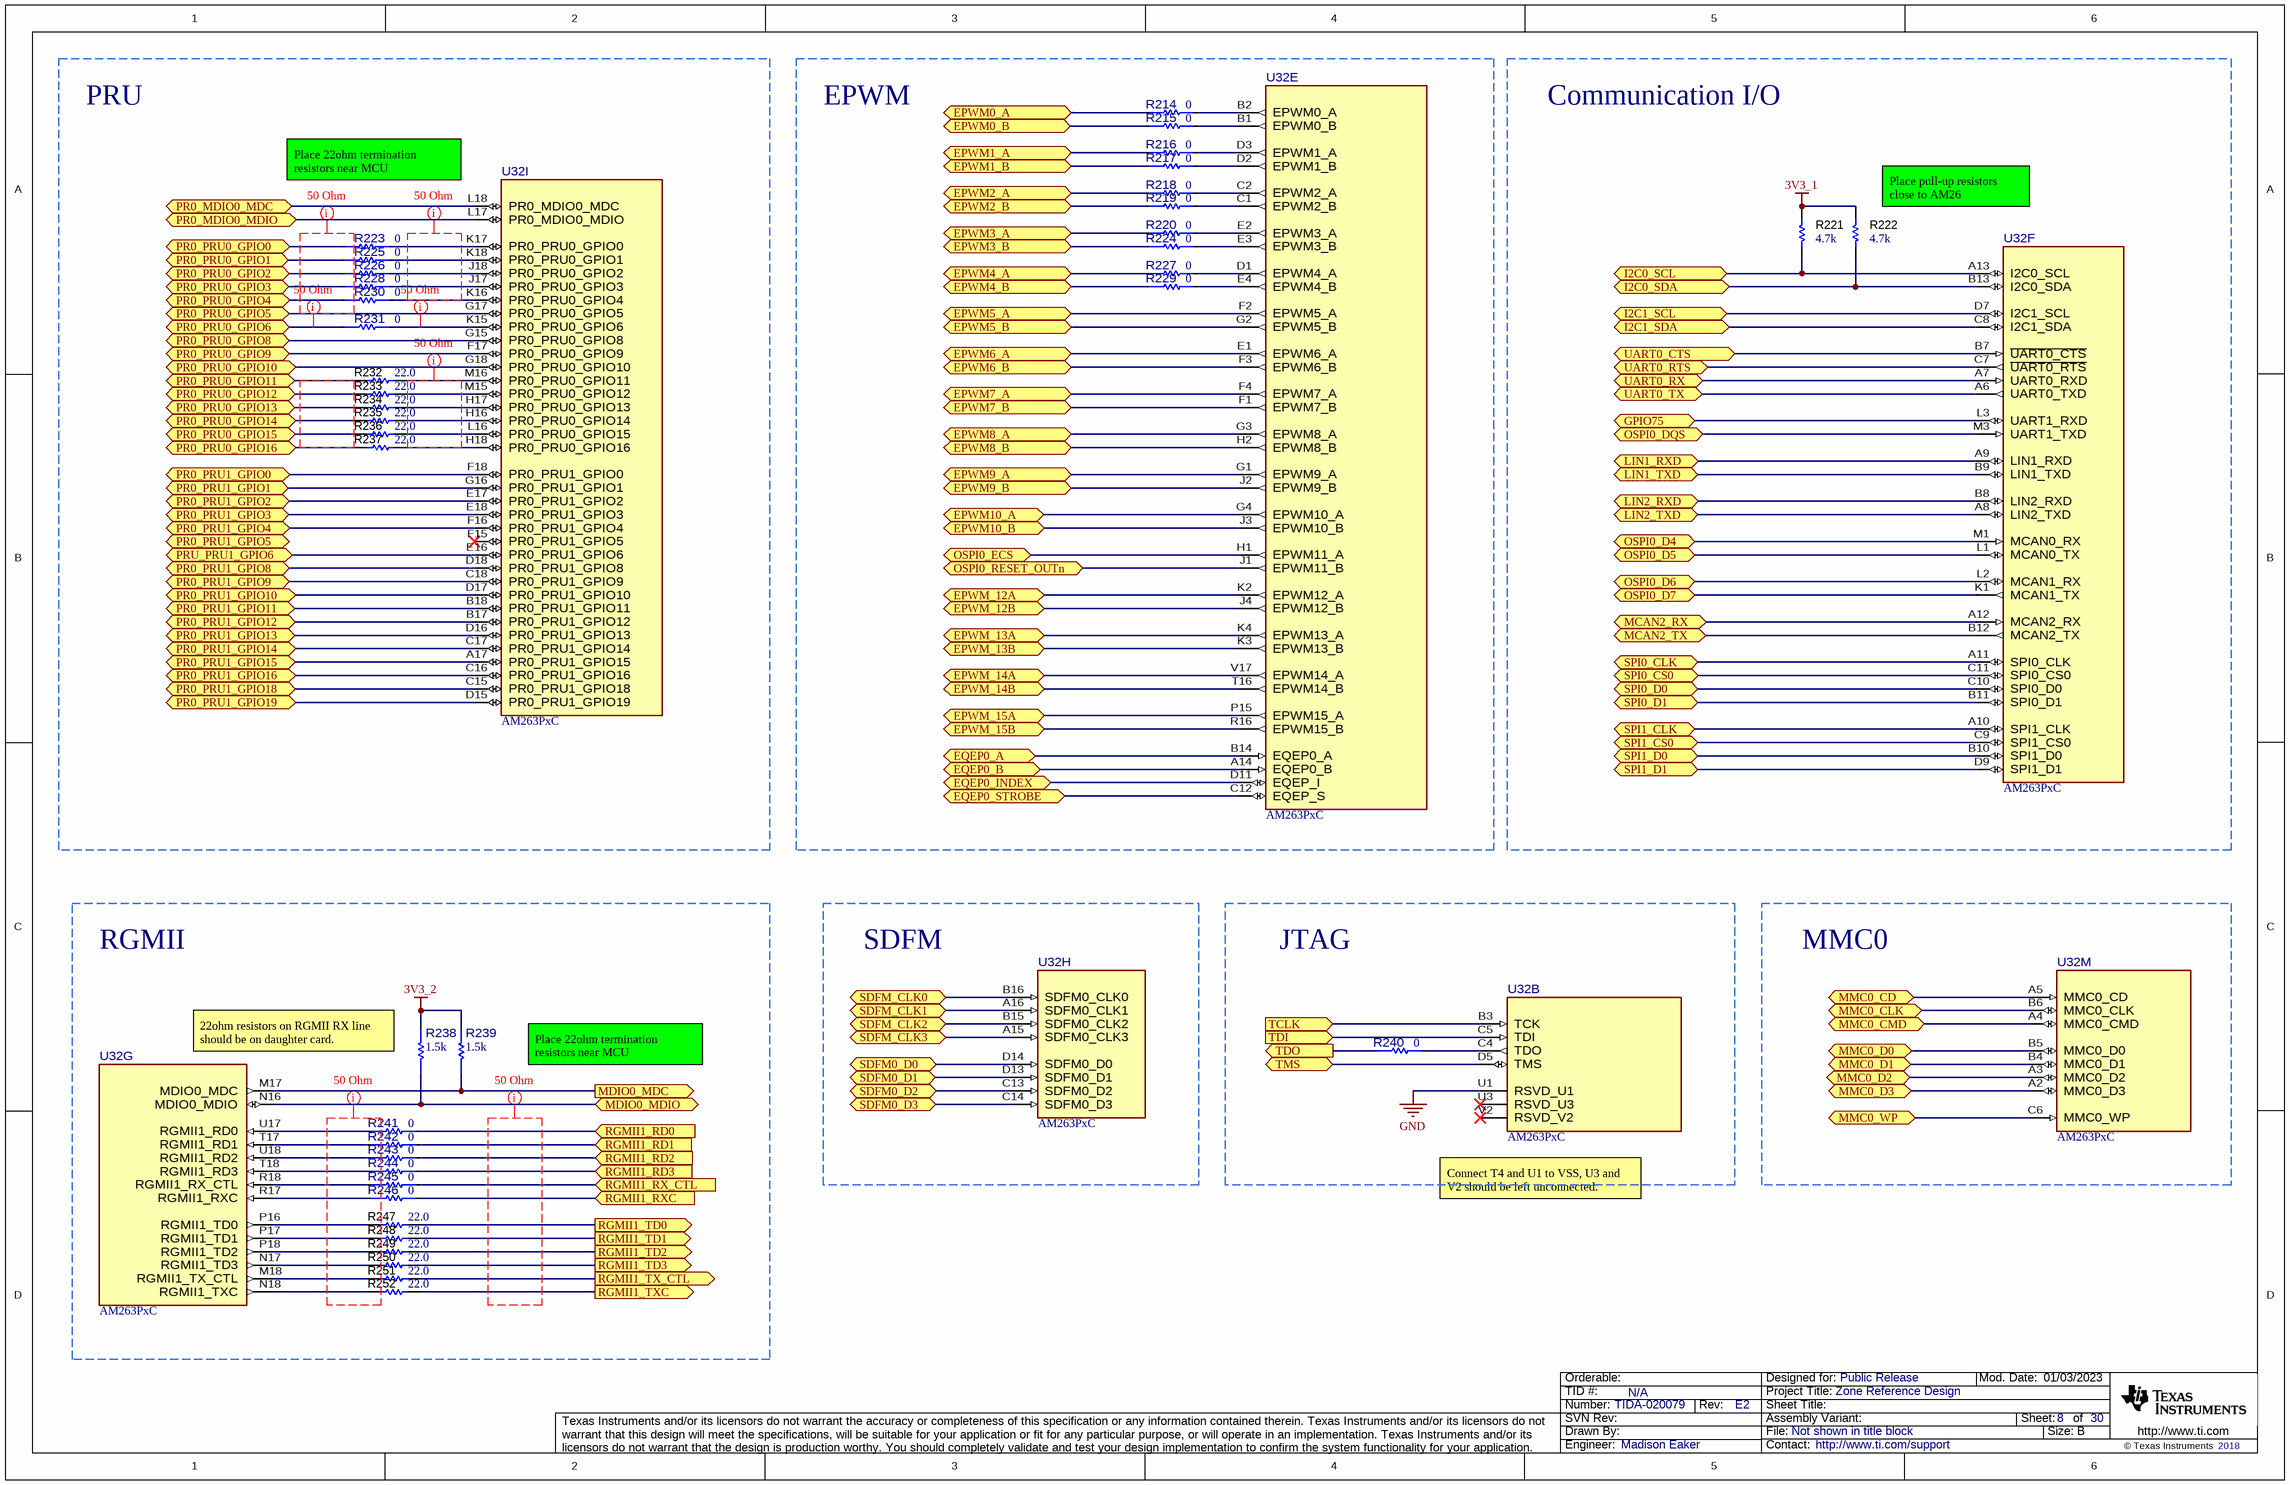
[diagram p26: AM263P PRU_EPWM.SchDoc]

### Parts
R214  value 0  [FP-ERJ-2GE0R00X_0402-MFG]  (hidden comment: ERJ-2GE0R00X)
R215  value 0  [FP-ERJ-2GE0R00X_0402-MFG]  (hidden comment: ERJ-2GE0R00X)
R216  value 0  [FP-ERJ-2GE0R00X_0402-MFG]  (hidden comment: ERJ-2GE0R00X)
R217  value 0  [FP-ERJ-2GE0R00X_0402-MFG]  (hidden comment: ERJ-2GE0R00X)
R218  value 0  [FP-ERJ-2GE0R00X_0402-MFG]  (hidden comment: ERJ-2GE0R00X)
R219  value 0  [FP-ERJ-2GE0R00X_0402-MFG]  (hidden comment: ERJ-2GE0R00X)
R220  value 0  [FP-ERJ-2GE0R00X_0402-MFG]  (hidden comment: ERJ-2GE0R00X)
R221  value 4.7k  [0402]  (hidden comment: CRCW04024K70JNED)
R222  value 4.7k  [0402]  (hidden comment: CRCW04024K70JNED)
R223  value 0  [FP-RMCF0201ZT0R00_0201-MFG]  (hidden comment: RMCF0201ZT0R00)
R224  value 0  [FP-ERJ-2GE0R00X_0402-MFG]  (hidden comment: ERJ-2GE0R00X)
R225  value 0  [FP-RMCF0201ZT0R00_0201-MFG]  (hidden comment: RMCF0201ZT0R00)
R226  value 0  [FP-RMCF0201ZT0R00_0201-MFG]  (hidden comment: RMCF0201ZT0R00)
R227  value 0  [FP-ERJ-2GE0R00X_0402-MFG]  (hidden comment: ERJ-2GE0R00X)
R228  value 0  [FP-RMCF0201ZT0R00_0201-IPC_C]  (hidden comment: RMCF0201ZT0R00)
R229  value 0  [FP-ERJ-2GE0R00X_0402-MFG]  (hidden comment: ERJ-2GE0R00X)
R230  value 0  [FP-RMCF0201ZT0R00_0201-MFG]  (hidden comment: RMCF0201ZT0R00)
R231  value 0  [FP-RMCF0201ZT0R00_0201-MFG]  (hidden comment: RMCF0201ZT0R00)
R232  ValueDisplayed: 22.0  [0201]  (hidden comment: RC0201FR-0722RL)
R233  ValueDisplayed: 22.0  [0201]  (hidden comment: RC0201FR-0722RL)
R234  ValueDisplayed: 22.0  [0201]  (hidden comment: RC0201FR-0722RL)
R235  ValueDisplayed: 22.0  [0201]  (hidden comment: RC0201FR-0722RL)
R236  ValueDisplayed: 22.0  [0201]  (hidden comment: RC0201FR-0722RL)
R237  ValueDisplayed: 22.0  [0201]  (hidden comment: RC0201FR-0722RL)
R238  value 1.5k  [FP-ERJ-2GEJ152X_0402-MFG]  (hidden comment: ERJ-2GEJ152X)
R239  value 1.5k  [FP-ERJ-2GEJ152X_0402-MFG]  (hidden comment: ERJ-2GEJ152X)
R240  value 0  [FP-ERJ-2GE0R00X_0402-MFG]  (hidden comment: ERJ-2GE0R00X)
R241  value 0  [FP-RMCF0201ZT0R00_0201-MFG]  (hidden comment: RMCF0201ZT0R00)
R242  value 0  [FP-RMCF0201ZT0R00_0201-MFG]  (hidden comment: RMCF0201ZT0R00)
R243  value 0  [FP-RMCF0201ZT0R00_0201-MFG]  (hidden comment: RMCF0201ZT0R00)
R244  value 0  [FP-RMCF0201ZT0R00_0201-MFG]  (hidden comment: RMCF0201ZT0R00)
R245  value 0  [FP-RMCF0201ZT0R00_0201-MFG]  (hidden comment: RMCF0201ZT0R00)
R246  value 0  [FP-RMCF0201ZT0R00_0201-MFG]  (hidden comment: RMCF0201ZT0R00)
R247  ValueDisplayed: 22.0  [0201]  (hidden comment: RC0201FR-0722RL)
R248  ValueDisplayed: 22.0  [0201]  (hidden comment: RC0201FR-0722RL)
R249  ValueDisplayed: 22.0  [0201]  (hidden comment: RC0201FR-0722RL)
R250  ValueDisplayed: 22.0  [0201]  (hidden comment: RC0201FR-0722RL)
R251  ValueDisplayed: 22.0  [0201]  (hidden comment: RC0201FR-0722RL)
R252  ValueDisplayed: 22.0  [0201]  (hidden comment: RC0201FR-0722RL)
U32  AM263PxC  [ZCZ0324A-MFG]  (parts B,E,F,G,H,I,M of 13)

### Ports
EPWM0_A (bidir), EPWM0_B (bidir), EPWM1_A (bidir), EPWM1_B (bidir), EPWM2_A (bidir), EPWM2_B (bidir), EPWM3_A (bidir), EPWM3_B (bidir), EPWM4_A (bidir), EPWM4_B (bidir), EPWM5_A (bidir), EPWM5_B (bidir), EPWM6_A (bidir), EPWM6_B (bidir), EPWM7_A (bidir), EPWM7_B (bidir), EPWM8_A (bidir), EPWM8_B (bidir), EPWM9_A (bidir), EPWM9_B (bidir), EPWM10_A (bidir), EPWM10_B (bidir), EPWM_12A (bidir), EPWM_12B (bidir), EPWM_13A (bidir), EPWM_13B (bidir), EPWM_14A (bidir), EPWM_14B (bidir), EPWM_15A (bidir), EPWM_15B (bidir), EQEP0_A (bidir), EQEP0_B (bidir), EQEP0_INDEX (bidir), EQEP0_STROBE (bidir), GPIO75 (bidir), I2C0_SCL (bidir), I2C0_SDA (bidir), I2C1_SCL (bidir), I2C1_SDA (bidir), LIN1_RXD (bidir), LIN1_TXD (bidir), LIN2_RXD (bidir), LIN2_TXD (bidir), MCAN2_RX (bidir), MCAN2_TX (bidir), MDIO0_MDC (out), MDIO0_MDIO (bidir), MMC0_CD (bidir), MMC0_CLK (bidir), MMC0_CMD (bidir), MMC0_D0 (bidir), MMC0_D1 (bidir), MMC0_D2 (bidir), MMC0_D3 (bidir), MMC0_WP (bidir), OSPI0_D4 (bidir), OSPI0_D5 (bidir), OSPI0_D6 (bidir), OSPI0_D7 (bidir), OSPI0_DQS (bidir), OSPI0_ECS (bidir), OSPI0_RESET_OUTn (bidir), PR0_MDIO0_MDC (bidir), PR0_MDIO0_MDIO (bidir), PR0_PRU0_GPIO0 (bidir), PR0_PRU0_GPIO1 (bidir), PR0_PRU0_GPIO2 (bidir), PR0_PRU0_GPIO3 (bidir), PR0_PRU0_GPIO4 (bidir), PR0_PRU0_GPIO5 (bidir), PR0_PRU0_GPIO6 (bidir), PR0_PRU0_GPIO8 (bidir), PR0_PRU0_GPIO9 (bidir), PR0_PRU0_GPIO10 (bidir), PR0_PRU0_GPIO11 (bidir), PR0_PRU0_GPIO12 (bidir), PR0_PRU0_GPIO13 (bidir), PR0_PRU0_GPIO14 (bidir), PR0_PRU0_GPIO15 (bidir), PR0_PRU0_GPIO16 (bidir), PR0_PRU1_GPIO0 (bidir), PR0_PRU1_GPIO1 (bidir), PR0_PRU1_GPIO2 (bidir), PR0_PRU1_GPIO3 (bidir), PR0_PRU1_GPIO4 (bidir), PR0_PRU1_GPIO5 (bidir), PR0_PRU1_GPIO8 (bidir), PR0_PRU1_GPIO9 (bidir), PR0_PRU1_GPIO10 (bidir), PR0_PRU1_GPIO11 (bidir), PR0_PRU1_GPIO12 (bidir), PR0_PRU1_GPIO13 (bidir), PR0_PRU1_GPIO14 (bidir), PR0_PRU1_GPIO15 (bidir), PR0_PRU1_GPIO16 (bidir), PR0_PRU1_GPIO18 (bidir), PR0_PRU1_GPIO19 (bidir), PRU_PRU1_GPIO6 (bidir), RGMII1_RD0 (in), RGMII1_RD1 (in), RGMII1_RD2 (in), RGMII1_RD3 (in), RGMII1_RX_CTL (in), RGMII1_RXC (in), RGMII1_TD0 (out), RGMII1_TD1 (out), RGMII1_TD2 (out), RGMII1_TD3 (out), RGMII1_TX_CTL (out), RGMII1_TXC (out), SDFM0_D0 (bidir), SDFM0_D1 (bidir), SDFM0_D2 (bidir), SDFM0_D3 (bidir), SDFM_CLK0 (bidir), SDFM_CLK1 (bidir), SDFM_CLK2 (bidir), SDFM_CLK3 (bidir), SPI0_CLK (bidir), SPI0_CS0 (bidir), SPI0_D0 (bidir), SPI0_D1 (bidir), SPI1_CLK (bidir), SPI1_CS0 (bidir), SPI1_D0 (bidir), SPI1_D1 (bidir), TCLK (in), TDI (in), TDO (out), TMS (bidir), UART0_CTS (bidir), UART0_RTS (bidir), UART0_RX (bidir), UART0_TX (bidir)

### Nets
3V3_1: R221.2 R222.2
3V3_2: R238.2 R239.2
GND: U32.U1(RSVD_U1)
A0_TMUX1308: U32.B4(MMC0_D1) ; port MMC0_D1
A1_TMUX1308: U32.A2(MMC0_D3) ; port MMC0_D3
A2_TMUX1308: U32.C6(MMC0_WP) ; port MMC0_WP
BIST_EN_TPS3762: U32.A15(SDFM0_CLK3) ; port SDFM_CLK3
BIST_TPS3762: U32.C14(SDFM0_D3) ; port SDFM0_D3
CAN2_RXD: U32.A12(MCAN2_RX) ; port MCAN2_RX
CAN2_TXD: U32.B12(MCAN2_TX) ; port MCAN2_TX
CAN5_RXD: U32.C16(PR0_PRU1_GPIO16) ; port PR0_PRU1_GPIO16
CAN5_TXD: U32.A17(PR0_PRU1_GPIO15) ; port PR0_PRU1_GPIO15
CAN6_RXD: U32.B18(PR0_PRU1_GPIO11) ; port PR0_PRU1_GPIO11
CAN6_TXD: U32.B17(PR0_PRU1_GPIO12) ; port PR0_PRU1_GPIO12
CAN7_RXD: U32.D16(PR0_PRU1_GPIO13) ; port PR0_PRU1_GPIO13
CAN7_TXD: U32.C17(PR0_PRU1_GPIO14) ; port PR0_PRU1_GPIO14
ClassD_AMP_SDIN_1: U32.G18(PR0_PRU0_GPIO10) ; port PR0_PRU0_GPIO10
ClassD_AMP_SDOUT_1: U32.F17(PR0_PRU0_GPIO9) ; port PR0_PRU0_GPIO9
CRS_DV/RX_CTRL_ETH1: R245.2 ; port RGMII1_RX_CTL
CRS_DV/RX_CTRL_ETH2: R230.1 ; port PR0_PRU0_GPIO4
CS_IO: R219.1 ; port EPWM2_B
CS_IO_1_MCU: U32.F4(EPWM7_A) ; port EPWM7_A
CS_LD_1_MCU: U32.J4(EPWM12_B) ; port EPWM_12B
CS_LD_4: U32.K3(EPWM13_B) ; port EPWM_13B
CS_PMIC_MCU: U32.D7(I2C1_SCL) ; port I2C1_SCL
EN1_TLIN1024A: U32.A5(MMC0_CD) ; port MMC0_CD
EN/IN1_DRV8245: R214.1 ; port EPWM0_A
EN_INA186: U32.B10(SPI1_D0) ; port SPI1_D0
EN_TCAN1043A: U32.B16(SDFM0_CLK0) ; port SDFM_CLK0
EPWM0_B: R215.1 ; port EPWM0_B
EPWM1_A: R216.1 ; port EPWM1_A
EPWM1_B: R217.1 ; port EPWM1_B
EPWM2_A: R218.1 ; port EPWM2_A
EPWM3_A: R220.1 ; port EPWM3_A
EPWM3_B: R224.1 ; port EPWM3_B
EPWM4_A: R227.1 ; port EPWM4_A
EPWM4_B: R229.1 ; port EPWM4_B
EPWM5_A: U32.F2(EPWM5_A) ; port EPWM5_A
EPWM5_B: U32.G2(EPWM5_B) ; port EPWM5_B
EPWM6_A: U32.E1(EPWM6_A) ; port EPWM6_A
EPWM6_B: U32.F3(EPWM6_B) ; port EPWM6_B
EPWM7_B: U32.F1(EPWM7_B) ; port EPWM7_B
EPWM8_A: U32.G3(EPWM8_A) ; port EPWM8_A
EPWM9_A: U32.G1(EPWM9_A) ; port EPWM9_A
EPWM9_B: U32.J2(EPWM9_B) ; port EPWM9_B
EPWM10_A: U32.G4(EPWM10_A) ; port EPWM10_A
EPWM_13A: U32.K4(EPWM13_A) ; port EPWM_13A
EPWM_14A: U32.V17(EPWM14_A) ; port EPWM_14A
EPWM_14B: U32.T16(EPWM14_B) ; port EPWM_14B
EPWM_15A: U32.P15(EPWM15_A) ; port EPWM_15A
EQEP0_A: U32.B14(EQEP0_A) ; port EQEP0_A
EQEP0_B: U32.A14(EQEP0_B) ; port EQEP0_B
EQEP0_STROBE: U32.C12(EQEP_S) ; port EQEP0_STROBE
FG_LM74704_MCU: U32.D9(SPI1_D1) ; port SPI1_D1
GPIO14: U32.B11(SPI0_D1) ; port SPI0_D1
GPIO75: U32.L3(UART1_RXD) ; port GPIO75
GPIO79: U32.B5(MMC0_D0) ; port MMC0_D0
GPIO81: U32.A3(MMC0_D2) ; port MMC0_D2
GPIO85: U32.L17(PR0_MDIO0_MDIO) ; port PR0_MDIO0_MDIO
GPIO86: U32.L18(PR0_MDIO0_MDC) ; port PR0_MDIO0_MDC
GPIO107: U32.E16(PR0_PRU1_GPIO6) ; port PRU_PRU1_GPIO6
GPIO108: U32.F16(PR0_PRU1_GPIO4) ; port PR0_PRU1_GPIO4
GPIO112: U32.E18(PR0_PRU1_GPIO3) ; port PR0_PRU1_GPIO3
GPIO124: U32.A16(SDFM0_CLK1) ; port SDFM_CLK1
GPIO125: U32.D13(SDFM0_D1) ; port SDFM0_D1
I2C0_SCL: R221.1 U32.A13(I2C0_SCL) ; port I2C0_SCL
I2C0_SDA: R222.1 U32.B13(I2C0_SDA) ; port I2C0_SDA
I2C1_SDA: U32.C8(I2C1_SDA) ; port I2C1_SDA
I2S_FSYNC_ETH_MCU: U32.G15(PR0_PRU0_GPIO8) ; port PR0_PRU0_GPIO8
I2S_SCLK_ETH_MCU: U32.G17(PR0_PRU0_GPIO5) ; port PR0_PRU0_GPIO5
LIN0_RXD: U32.B6(MMC0_CLK) ; port MMC0_CLK
LIN0_TXD: U32.A4(MMC0_CMD) ; port MMC0_CMD
LIN1_RXD: U32.A9(LIN1_RXD) ; port LIN1_RXD
LIN1_TXD: U32.B9(LIN1_TXD) ; port LIN1_TXD
LIN2_RXD: U32.B8(LIN2_RXD) ; port LIN2_RXD
LIN2_TXD: U32.A8(LIN2_TXD) ; port LIN2_TXD
LIN3_RXD: U32.C11(SPI0_CS0) ; port SPI0_CS0
LIN4_RXD: U32.A10(SPI1_CLK) ; port SPI1_CLK
LIN4_TXD: U32.C9(SPI1_CS0) ; port SPI1_CS0
MCU_INTn: U32.D14(SDFM0_D0) ; port SDFM0_D0
MDC_ETH: R239.1 U32.M17(MDIO0_MDC) ; port MDIO0_MDC
MDIO_ETH: R238.1 U32.N16(MDIO0_MDIO) ; port MDIO0_MDIO
nCS: U32.K2(EPWM12_A) ; port EPWM_12A
OA3_ED/SPI_CS_ETH3: U32.F18(PR0_PRU1_GPIO0) ; port PR0_PRU1_GPIO0
OA3_RX_ETH3: U32.G16(PR0_PRU1_GPIO1) ; port PR0_PRU1_GPIO1
OA3_TX_ETH3: U32.E17(PR0_PRU1_GPIO2) ; port PR0_PRU1_GPIO2
OSPI0_D4: U32.M1(MCAN0_RX) ; port OSPI0_D4
OSPI0_D5: U32.L1(MCAN0_TX) ; port OSPI0_D5
OSPI0_D6: U32.L2(MCAN1_RX) ; port OSPI0_D6
OSPI0_D7: U32.K1(MCAN1_TX) ; port OSPI0_D7
OSPI0_DQS: U32.M3(UART1_TXD) ; port OSPI0_DQS
OSPI0_ECS: U32.H1(EPWM11_A) ; port OSPI0_ECS
OSPI0_RESET_OUTn: U32.J1(EPWM11_B) ; port OSPI0_RESET_OUTn
PR0_PRU0_GPIO0: R223.1 ; port PR0_PRU0_GPIO0
PR0_PRU0_GPIO1: R225.1 ; port PR0_PRU0_GPIO1
PR0_PRU0_GPIO2: R226.1 ; port PR0_PRU0_GPIO2
PR0_PRU0_GPIO3: R228.1 ; port PR0_PRU0_GPIO3
PR0_PRU0_GPIO6: R231.1 ; port PR0_PRU0_GPIO6
PR0_PRU0_GPIO11: R232.1 ; port PR0_PRU0_GPIO11
PR0_PRU0_GPIO12: R233.1 ; port PR0_PRU0_GPIO12
PR0_PRU0_GPIO13: R234.1 ; port PR0_PRU0_GPIO13
PR0_PRU0_GPIO14: R235.1 ; port PR0_PRU0_GPIO14
PR0_PRU0_GPIO15: R236.1 ; port PR0_PRU0_GPIO15
PR0_PRU0_GPIO16: R237.1 ; port PR0_PRU0_GPIO16
PR0_PRU1_GPIO8: U32.D18(PR0_PRU1_GPIO8) ; port PR0_PRU1_GPIO8
PR0_PRU1_GPIO9: U32.C18(PR0_PRU1_GPIO9) ; port PR0_PRU1_GPIO9
PR0_PRU1_GPIO10: U32.D17(PR0_PRU1_GPIO10) ; port PR0_PRU1_GPIO10
PR0_PRU1_GPIO18: U32.C15(PR0_PRU1_GPIO18) ; port PR0_PRU1_GPIO18
PR0_PRU1_GPIO19: U32.D15(PR0_PRU1_GPIO19) ; port PR0_PRU1_GPIO19
PWM_ETH: U32.R16(EPWM15_B) ; port EPWM_15B
RGMII1_RD0: R241.2 ; port RGMII1_RD0
RGMII1_RD1: R242.2 ; port RGMII1_RD1
RGMII1_RD2: R243.2 ; port RGMII1_RD2
RGMII1_RD3: R244.2 ; port RGMII1_RD3
RGMII1_RXC: R246.2 ; port RGMII1_RXC
RGMII1_TD0: R247.2 ; port RGMII1_TD0
RGMII1_TD1: R248.2 ; port RGMII1_TD1
RGMII1_TD2: R249.2 ; port RGMII1_TD2
RGMII1_TD3: R250.2 ; port RGMII1_TD3
RGMII1_TX_CTL: R251.2 ; port RGMII1_TX_CTL
RGMII1_TXC: R252.2 ; port RGMII1_TXC
RXD2_TCAN1046_UART: U32.C13(SDFM0_D2) ; port SDFM0_D2
SDFM_CLK2: U32.B15(SDFM0_CLK2) ; port SDFM_CLK2
SDO_IO: U32.H2(EPWM8_B) ; port EPWM8_B
SDO_LD: U32.J3(EPWM10_B) ; port EPWM10_B
SDO_PMIC: U32.C7(~{UART0_RTS}) ; port UART0_RTS
SPI0_CLK: U32.A11(SPI0_CLK) ; port SPI0_CLK
SPI0_D0: U32.C10(SPI0_D0) ; port SPI0_D0
SPI6_CS3: U32.D11(EQEP_I) ; port EQEP0_INDEX
TCLK: U32.B3(TCK) ; port TCLK
TDI: U32.C5(TDI) ; port TDI
TDO: R240.1 ; port TDO
TMS: U32.D5(TMS) ; port TMS
UART0_CTS: U32.B7(~{UART0_CTS}) ; port UART0_CTS
UART0_RX: U32.A7(UART0_RXD) ; port UART0_RX
UART0_TX: U32.A6(UART0_TXD) ; port UART0_TX
NetR214_2: R214.2 U32.B2(EPWM0_A)
NetR215_2: R215.2 U32.B1(EPWM0_B)
NetR216_2: R216.2 U32.D3(EPWM1_A)
NetR217_2: R217.2 U32.D2(EPWM1_B)
NetR218_2: R218.2 U32.C2(EPWM2_A)
NetR219_2: R219.2 U32.C1(EPWM2_B)
NetR220_2: R220.2 U32.E2(EPWM3_A)
NetR223_2: R223.2 U32.K17(PR0_PRU0_GPIO0)
NetR224_2: R224.2 U32.E3(EPWM3_B)
NetR225_2: R225.2 U32.K18(PR0_PRU0_GPIO1)
NetR226_2: R226.2 U32.J18(PR0_PRU0_GPIO2)
NetR227_2: R227.2 U32.D1(EPWM4_A)
NetR228_2: R228.2 U32.J17(PR0_PRU0_GPIO3)
NetR229_2: R229.2 U32.E4(EPWM4_B)
NetR230_2: R230.2 U32.K16(PR0_PRU0_GPIO4)
NetR231_2: R231.2 U32.K15(PR0_PRU0_GPIO6)
NetR232_2: R232.2 U32.M16(PR0_PRU0_GPIO11)
NetR233_2: R233.2 U32.M15(PR0_PRU0_GPIO12)
NetR234_2: R234.2 U32.H17(PR0_PRU0_GPIO13)
NetR235_2: R235.2 U32.H16(PR0_PRU0_GPIO14)
NetR236_2: R236.2 U32.L16(PR0_PRU0_GPIO15)
NetR237_2: R237.2 U32.H18(PR0_PRU0_GPIO16)
NetR240_2: R240.2 U32.C4(TDO)
NetR241_1: R241.1 U32.U17(RGMII1_RD0)
NetR242_1: R242.1 U32.T17(RGMII1_RD1)
NetR243_1: R243.1 U32.U18(RGMII1_RD2)
NetR244_1: R244.1 U32.T18(RGMII1_RD3)
NetR245_1: R245.1 U32.R18(RGMII1_RX_CTL)
NetR246_1: R246.1 U32.R17(RGMII1_RXC)
NetR247_1: R247.1 U32.P16(RGMII1_TD0)
NetR248_1: R248.1 U32.P17(RGMII1_TD1)
NetR249_1: R249.1 U32.P18(RGMII1_TD2)
NetR250_1: R250.1 U32.N17(RGMII1_TD3)
NetR251_1: R251.1 U32.M18(RGMII1_TX_CTL)
NetR252_1: R252.1 U32.N18(RGMII1_TXC)

Not connected (* = marked no-connect by the designer): U32 F15(PR0_PRU1_GPIO5)* U3(RSVD_U3)* V2(RSVD_V2)*

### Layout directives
net class 50ohm: 3V3_2, (no net found under the mark), NetR231_2, NetR232_2, PR0_PRU0_GPIO6

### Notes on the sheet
- PRU
- EPWM
- Communication I/O
- Place 22ohm termination resistors near MCU
- (near R222) Place pull-up resistors close to AM26
- RGMII
- SDFM
- JTAG
- MMC0
- 22ohm resistors on RGMII RX line should be on daughter card.
- (near U32) Connect T4 and U1 to VSS, U3 and V2 should be left unconnected.

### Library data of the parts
R214-R220 R224 R227 R229 R240 = CMP-0002710-1: as R253 on sheet AM263P OSPI Bootmode
R221 R222 = CMP-0026938-5: RES, 4.7 k, 5%, 0.063 W, AEC-Q200 Grade 0, 0402; Manufacturer: Vishay-Dale; Power_W: 63mW; TempCo: 200 ppm/C; Value_Code: 4k70; SizeX_mm: 1; SizeY_mm: 0.5; SizeZ_mm: 0.6; Value2: 0.063W; AEC Qualified: Y; AEC Grade: 0; AEC Category: Q200; EIA_Code: E24; VDC_V: 50V
R223 R225 R226 R228 R230 R231 R241-R246 = CMP-0033520-1: 0Ω ±0 0.05W 0201 Thick Film Chip Resistor AEC-Q200 compliant; Manufacturer: Stackpole Electronics; AEC Grade: Grade 0; AEC Qualified: Yes; Power_W: 50mW; SizeZ_mm: 0.26mm; VDC_V: 25V
R232-R237 R247-R252 = CMP-0027500-1: as R266-R274 on sheet AM263P OSPI Bootmode
R238 R239 = CMP-0042990-1: Res Thick Film 0402 1.5K Ohm 5% 1/10W ±200ppm/°C Molded SMD Punched Carrier T/R; Manufacturer: Panasonic; AEC Grade: Grade 0; AEC Qualified: Yes; Power_W: 100mW; SizeZ_mm: 0.4mm; VDC_V: 50V; Category 5A00970A6D5C81C7: Uncategorized; Category 5C6A91606D4187Ad: Resistors; Category 7542B8484461Ae85: Passive Components; Category Cd01000Bfc2916C6: Single Components
U32 = CMP-0001698-2: as U32 on sheet AM263P OSPI Bootmode

## Sheet Ethernet.SchDoc
size 431 x 279 mm; Date: Not shown in title block; ApprovedBy: Not shown in title block; CheckedBy: Not shown in title block; Author: Not shown in title block; CompanyName: Not shown in title block; Engineer: Not shown in title block; Organization: Not shown in title block; Address1: Not shown in title block; Address2: Not shown in title block; Address3: Not shown in title block; Address4: Not shown in title block; DocumentNumber: 1; Revision: Use project parameter SCH_Rev; SheetNumber: 24; SheetTotal: 30; PageSetup: Record=PageOptions¦CenterHorizontal=True¦CenterVertical=True¦PrintScale=1.00¦XCorrection=1.00¦YCorrection=1.00¦PrintKind=0¦BorderSize=5000000¦LeftOffset=0¦BottomOffset=0¦Orientation=2¦PaperLength=1000¦PaperWidth=1000¦Scale=100¦PaperSource=15¦PrintQuality=600¦MediaType=1¦DitherType=10¦PaperKind=Letter¦PrintScaleMode=1
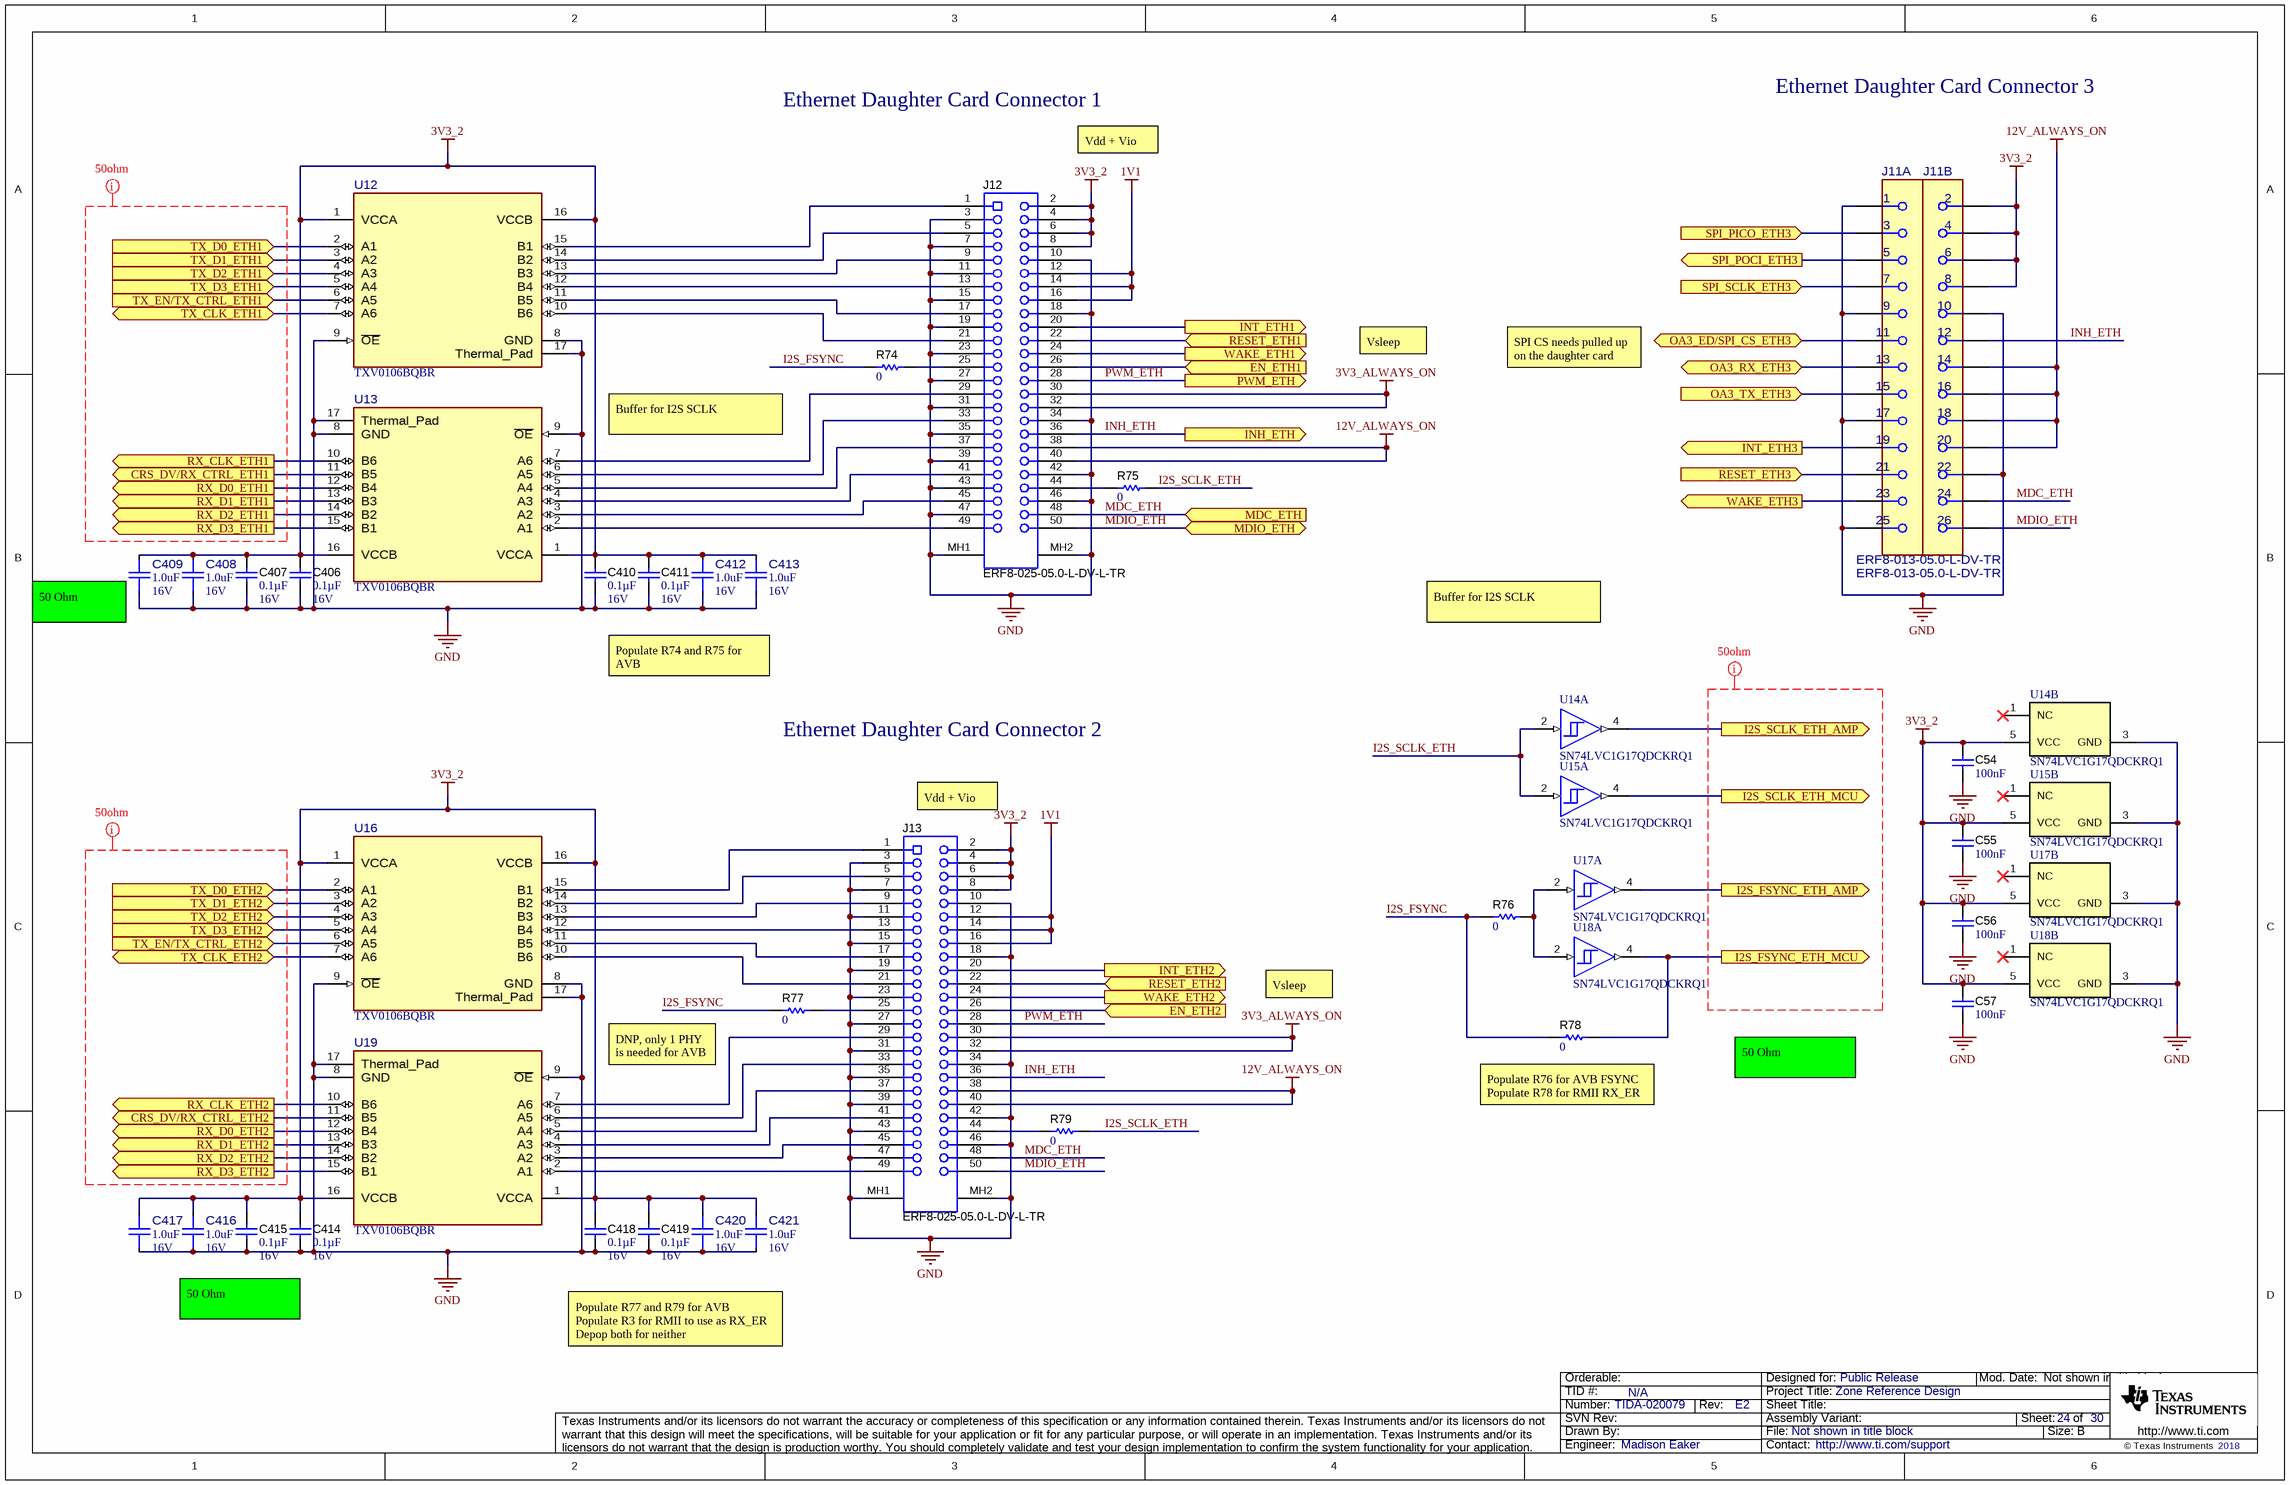
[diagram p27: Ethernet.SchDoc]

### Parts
C54  Cap_F: 100nF  [0603]  (hidden comment: HMK107B7104KAHT)
C55  Cap_F: 100nF  [0603]  (hidden comment: HMK107B7104KAHT)
C56  Cap_F: 100nF  [0603]  (hidden comment: HMK107B7104KAHT)
C57  Cap_F: 100nF  [0603]  (hidden comment: HMK107B7104KAHT)
C406  ValueDisplayed: 0.1µF  VDC_V: 16V  [0201_033L]  (hidden comment: 0201BB104KW160)
C407  ValueDisplayed: 0.1µF  VDC_V: 16V  [0201_033L]  (hidden comment: 0201BB104KW160)
C408  ValueDisplayed: 1.0uF  VDC_V: 16V  [FP-GRM033R61C105ME15D_0201-MFG]  (hidden comment: GRM033R61C105ME15D)
C409  ValueDisplayed: 1.0uF  VDC_V: 16V  [FP-GRM033R61C105ME15D_0201-MFG]  (hidden comment: GRM033R61C105ME15D)
C410  ValueDisplayed: 0.1µF  VDC_V: 16V  [0201_033L]  (hidden comment: 0201BB104KW160)
C411  ValueDisplayed: 0.1µF  VDC_V: 16V  [0201_033L]  (hidden comment: 0201BB104KW160)
C412  ValueDisplayed: 1.0uF  VDC_V: 16V  [FP-GRM033R61C105ME15D_0201-MFG]  (hidden comment: GRM033R61C105ME15D)
C413  ValueDisplayed: 1.0uF  VDC_V: 16V  [FP-GRM033R61C105ME15D_0201-MFG]  (hidden comment: GRM033R61C105ME15D)
C414  ValueDisplayed: 0.1µF  VDC_V: 16V  [0201_033L]  (hidden comment: 0201BB104KW160)
C415  ValueDisplayed: 0.1µF  VDC_V: 16V  [0201_033L]  (hidden comment: 0201BB104KW160)
C416  ValueDisplayed: 1.0uF  VDC_V: 16V  [FP-GRM033R61C105ME15D_0201-MFG]  (hidden comment: GRM033R61C105ME15D)
C417  ValueDisplayed: 1.0uF  VDC_V: 16V  [FP-GRM033R61C105ME15D_0201-MFG]  (hidden comment: GRM033R61C105ME15D)
C418  ValueDisplayed: 0.1µF  VDC_V: 16V  [0201_033L]  (hidden comment: 0201BB104KW160)
C419  ValueDisplayed: 0.1µF  VDC_V: 16V  [0201_033]  (hidden comment: 0201BB104KW160)
C420  ValueDisplayed: 1.0uF  VDC_V: 16V  [FP-GRM033R61C105ME15D_0201-MFG]  (hidden comment: GRM033R61C105ME15D)
C421  ValueDisplayed: 1.0uF  VDC_V: 16V  [FP-GRM033R61C105ME15D_0201-MFG]  (hidden comment: GRM033R61C105ME15D)
J11  ERF8-013-05.0-L-DV-TR  [FP-ERF8-013-05.0-L-DV-TR_CONN_RCPT26-MFG]  (parts A,B of 2)
J12  ERF8-025-05.0-L-DV-L-TR  [Samtec_ERF8-025-05_0-x-DV-L]
J13  ERF8-025-05.0-L-DV-L-TR  [Samtec_ERF8-025-05_0-x-DV-L]
R74  ValueDisplayed: 0  [0603]  (hidden comment: RC0603JR-070RL)
R75  ValueDisplayed: 0  [0603]  (hidden comment: RC0603JR-070RL)
R76  ValueDisplayed: 0  [0603]  (hidden comment: RC0603JR-070RL)
R77  ValueDisplayed: 0  [0603]  (hidden comment: RC0603JR-070RL)
R78  ValueDisplayed: 0  [0603]  (hidden comment: RC0603JR-070RL)
R79  ValueDisplayed: 0  [0603]  (hidden comment: RC0603JR-070RL)
U12  TXV0106BQBR  [BQB0016A-MFG]
U13  TXV0106BQBR  [BQB0016A-MFG]
U14  SN74LVC1G17QDCKRQ1  [DCK0005A_N]  (parts A,B of 2)
U15  SN74LVC1G17QDCKRQ1  [DCK0005A_N]  (parts A,B of 2)
U16  TXV0106BQBR  [BQB0016A-MFG]
U17  SN74LVC1G17QDCKRQ1  [DCK0005A_N]  (parts A,B of 2)
U18  SN74LVC1G17QDCKRQ1  [DCK0005A_N]  (parts A,B of 2)
U19  TXV0106BQBR  [BQB0016A-MFG]

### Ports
CRS_DV/RX_CTRL_ETH1 (out), CRS_DV/RX_CTRL_ETH2 (out), EN_ETH1 (in), EN_ETH2 (in), I2S_FSYNC_ETH_AMP (out), I2S_FSYNC_ETH_MCU (out), I2S_SCLK_ETH_AMP (out), I2S_SCLK_ETH_MCU (out), INH_ETH (out), INT_ETH1 (out), INT_ETH2 (out), INT_ETH3 (out), MDC_ETH (in), MDIO_ETH (bidir), OA3_ED/SPI_CS_ETH3 (bidir), OA3_RX_ETH3 (bidir), OA3_TX_ETH3 (in), PWM_ETH (out), RESET_ETH1 (in), RESET_ETH2 (in), RESET_ETH3 (in), RX_CLK_ETH1 (out), RX_CLK_ETH2 (out), RX_D0_ETH1 (out), RX_D0_ETH2 (out), RX_D1_ETH1 (out), RX_D1_ETH2 (out), RX_D2_ETH1 (out), RX_D2_ETH2 (out), RX_D3_ETH1 (out), RX_D3_ETH2 (out), SPI_PICO_ETH3 (in), SPI_POCI_ETH3 (out), SPI_SCLK_ETH3 (in), TX_CLK_ETH1 (bidir), TX_CLK_ETH2 (bidir), TX_D0_ETH1 (in), TX_D0_ETH2 (in), TX_D1_ETH1 (in), TX_D1_ETH2 (in), TX_D2_ETH1 (in), TX_D2_ETH2 (in), TX_D3_ETH1 (in), TX_D3_ETH2 (in), TX_EN/TX_CTRL_ETH1 (in), TX_EN/TX_CTRL_ETH2 (in), WAKE_ETH1 (out), WAKE_ETH2 (out), WAKE_ETH3 (out)

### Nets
1V1: J12.12 J12.14 J12.16 J13.12 J13.14 J13.16
3V3_2: C54.1 C55.1 C56.1 C57.1 C406.1 C407.1 C408.2 C409.2 C410.1 C411.1 C412.2 C413.2 C414.1 C415.1 C416.2 C417.2 C418.1 C419.1 C420.2 C421.2 J11.2 J11.4 J11.6 J11.8 J12.2 J12.4 J12.6 J12.8 J13.2 J13.4 J13.6 J13.8 U12.1(VCCA) U12.16(VCCB) U13.1(VCCA) U13.16(VCCB) U14.5(VCC) U15.5(VCC) U16.1(VCCA) U16.16(VCCB) U17.5(VCC) U18.5(VCC) U19.1(VCCA) U19.16(VCCB)
3V3_ALWAYS_ON: J12.30 J12.32 J13.30 J13.32
12V_ALWAYS_ON: J11.14 J11.16 J11.18 J11.20 J12.38 J12.40 J13.38 J13.40
GND: C54.2 C55.2 C56.2 C57.2 C406.2 C407.2 C408.1 C409.1 C410.2 C411.2 C412.1 C413.1 C414.2 C415.2 C416.1 C417.1 C418.2 C419.2 C420.1 C421.1 J11.1 J11.9 J11.10 J11.17 J11.22 J11.25 J12.3 J12.7 J12.10 J12.11 J12.15 J12.18 J12.19 J12.23 J12.27 J12.31 J12.34 J12.35 J12.39 J12.42 J12.43 J12.46 J12.47 J12.MH1 J12.MH2 J13.3 J13.7 J13.10 J13.11 J13.15 J13.18 J13.19 J13.23 J13.27 J13.31 J13.34 J13.35 J13.39 J13.42 J13.43 J13.46 J13.47 J13.MH1 J13.MH2 U12.8(GND) U12.9(~{OE}) U12.17(Thermal_Pad) U13.8(GND) U13.9(~{OE}) U13.17(Thermal_Pad) U14.3(GND) U15.3(GND) U16.8(GND) U16.9(~{OE}) U16.17(Thermal_Pad) U17.3(GND) U18.3(GND) U19.8(GND) U19.9(~{OE}) U19.17(Thermal_Pad)
ClassD_AMP_FSYNC: U17.4(Y) ; port I2S_FSYNC_ETH_AMP
ClassD_AMP_SCLk: U14.4(Y) ; port I2S_SCLK_ETH_AMP
CRS_DV/RX_CTRL_ETH1: U13.11(B5) ; port CRS_DV/RX_CTRL_ETH1
CRS_DV/RX_CTRL_ETH2: U19.11(B5) ; port CRS_DV/RX_CTRL_ETH2
EN_ETH: J12.26 J13.26 ; port EN_ETH1, port EN_ETH2
EPWM6_B: J13.20 ; port INT_ETH2
EPWM_14A: J12.20 ; port INT_ETH1
EPWM_14B: J11.23 J12.24 J13.24 ; port WAKE_ETH1, port WAKE_ETH3, port WAKE_ETH2
GPIO75: J11.19 ; port INT_ETH3
I2S_FSYNC: R74.1 R76.1 R77.1 R78.1  [project net I2S_FSYNC_24]
I2S_FSYNC_ETH_MCU: R78.2 U18.4(Y) ; port I2S_FSYNC_ETH_MCU
I2S_SCLK_ETH: R75.2 R79.2 U14.2(A) U15.2(A)  [project net I2S_SCLK_ETH_24]
I2S_SCLK_ETH_MCU: U15.4(Y) ; port I2S_SCLK_ETH_MCU
INH_ETH: J11.12 J12.36 J13.36 ; port INH_ETH
MDC_ETH: J11.24 J12.48 J13.48 ; port MDC_ETH
MDIO_ETH: J11.26 J12.50 J13.50 ; port MDIO_ETH
OA3_ED/SPI_CS_ETH3: J11.11 ; port OA3_ED/SPI_CS_ETH3
OA3_RX_ETH3: J11.13 ; port OA3_RX_ETH3
OA3_TX_ETH3: J11.15 ; port OA3_TX_ETH3
PR0_PRU0_GPIO0: U19.12(B4) ; port RX_D0_ETH2
PR0_PRU0_GPIO1: U19.13(B3) ; port RX_D1_ETH2
PR0_PRU0_GPIO2: U19.14(B2) ; port RX_D2_ETH2
PR0_PRU0_GPIO3: U19.15(B1) ; port RX_D3_ETH2
PR0_PRU0_GPIO6: U19.10(B6) ; port RX_CLK_ETH2
PR0_PRU0_GPIO11: U16.2(A1) ; port TX_D0_ETH2
PR0_PRU0_GPIO12: U16.3(A2) ; port TX_D1_ETH2
PR0_PRU0_GPIO13: U16.4(A3) ; port TX_D2_ETH2
PR0_PRU0_GPIO14: U16.5(A4) ; port TX_D3_ETH2
PR0_PRU0_GPIO15: U16.6(A5) ; port TX_EN/TX_CTRL_ETH2
PR0_PRU0_GPIO16: U16.7(A6) ; port TX_CLK_ETH2
PR0_PRU1_GPIO8: J11.5 ; port SPI_POCI_ETH3
PWM_ETH: J12.28 J13.28 ; port PWM_ETH
RESET_ETH: J11.21 J12.22 J13.22 ; port RESET_ETH1, port RESET_ETH3, port RESET_ETH2
RGMII1_RD0: U13.12(B4) ; port RX_D0_ETH1
RGMII1_RD1: U13.13(B3) ; port RX_D1_ETH1
RGMII1_RD2: U13.14(B2) ; port RX_D2_ETH1
RGMII1_RD3: U13.15(B1) ; port RX_D3_ETH1
RGMII1_RXC: U13.10(B6) ; port RX_CLK_ETH1
RGMII1_TD0: U12.2(A1) ; port TX_D0_ETH1
RGMII1_TD1: U12.3(A2) ; port TX_D1_ETH1
RGMII1_TD2: U12.4(A3) ; port TX_D2_ETH1
RGMII1_TD3: U12.5(A4) ; port TX_D3_ETH1
RGMII1_TX_CTL: U12.6(A5) ; port TX_EN/TX_CTRL_ETH1
RGMII1_TXC: U12.7(A6) ; port TX_CLK_ETH1
SPI5_CLK: J11.7 ; port SPI_SCLK_ETH3
SPI5_SDI: J11.3 ; port SPI_PICO_ETH3
NetJ12_1: J12.1 U12.15(B1)
NetJ12_5: J12.5 U12.14(B2)
NetJ12_9: J12.9 U12.13(B3)
NetJ12_13: J12.13 U12.12(B4)
NetJ12_17: J12.17 U12.11(B5)
NetJ12_21: J12.21 U12.10(B6)
NetJ12_25: J12.25 R74.2
NetJ12_29: J12.29 U13.7(A6)
NetJ12_33: J12.33 U13.6(A5)
NetJ12_37: J12.37 U13.5(A4)
NetJ12_41: J12.41 U13.4(A3)
NetJ12_44: J12.44 R75.1
NetJ12_45: J12.45 U13.3(A2)
NetJ12_49: J12.49 U13.2(A1)
NetJ13_1: J13.1 U16.15(B1)
NetJ13_5: J13.5 U16.14(B2)
NetJ13_9: J13.9 U16.13(B3)
NetJ13_13: J13.13 U16.12(B4)
NetJ13_17: J13.17 U16.11(B5)
NetJ13_21: J13.21 U16.10(B6)
NetJ13_25: J13.25 R77.2
NetJ13_29: J13.29 U19.7(A6)
NetJ13_33: J13.33 U19.6(A5)
NetJ13_37: J13.37 U19.5(A4)
NetJ13_41: J13.41 U19.4(A3)
NetJ13_44: J13.44 R79.1
NetJ13_45: J13.45 U19.3(A2)
NetJ13_49: J13.49 U19.2(A1)
NetR76_2: R76.2 U17.2(A) U18.2(A)

Not connected (* = marked no-connect by the designer): U14 1(NC)*; U15 1(NC)*; U17 1(NC)*; U18 1(NC)*

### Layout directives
net class 50ohm: (no net found under the mark)

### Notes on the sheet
- Ethernet Daughter Card Connector 3
- Ethernet Daughter Card Connector 1
- Vdd + Vio
- Vsleep
- SPI CS needs pulled up on the daughter card
- Buffer for I2S SCLK
- (near C409) 50 Ohm
- Populate R74 and R75 for AVB
  Otherwise Depop
- Ethernet Daughter Card Connector 2
- (near J13) Vdd + Vio
- DNP, only 1 PHY is needed for AVB
- (near R78) Populate R76 for AVB FSYNC
  Populate R78 for RMII RX_ER
- 50 Ohm
- Populate R77 and R79 for AVB
  Populate R3 for RMII to use as RX_ER
  Depop both for neither

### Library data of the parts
C54-C57 = CMP-0081011-1: CAP, CERM, 0.1 µF, 100 V,+/- 10%, X7R, AEC-Q200 Grade 1, 0603; Manufacturer: Taiyo Yuden; SizeAreaWB_mm2: 4.68; SizeArea_mm2: 1.28; AEC Qualified: Y; AEC Category: Q200; Value: 0.1uF; TaMax_C: 125°C; SizeZ_mm: 1; Polarized: N; TaMin_C: -55°C; SizeY_mm: 0.8; Value2: 100V; U/M: EA; SizeX_mm: 1.6; ValueDisplayed: 0.1µF
C406 C407 C410 C411 C414 C415 C418 C419 = CMP-0860981-1: CAP, CERM, 0.1 µF, 16 V,+/- 10%, X7R, 0201; Manufacturer: Passive Plus; Value: 0.1uF; Polarized: N; SizeY_mm: 0.3; TaMin_C: -55°C; U/M: EA; Cap_Case: 0201; AEC Category: Q200; SizeZ_mm: 0.33; SizeArea_mm2: 0.18; SizeX_mm: 0.6; Cap_F: 100nF; SizeAreaWB_mm2: 2.08; TaMax_C: 125°C
C408 C409 C412 C413 C416 C417 C420 C421 = CMP-0097126-1: Chip Multilayer Ceramic Capacitors for General Purpose, 0201, 1.0uF, X5R, 15%, 20%, 16V; Manufacturer: Murata; SizeZ_mm: 0.39mm; Cap_F: 1µF; Value: 1µF; AEC Qualified: No
J11 = CMP-0096961-1: 26 Position Connector Socket, Outer Shroud Contacts Surface Mount Gold; Manufacturer: Samtec; Is Female: yes; SizeZ_mm: 5.385mm; DUT-Pitch_mm: 0.8mm; Conn Orientation: Vertical; Current_A: 1.4A; AEC Qualified: No; Voltage_V: 225V; ContactFinish: Gold,Nickel; Row_Count: 2; Conn Gender: Female
J12 J13 = CMP-0055635-1: Receptacle, 0.8mm, 25x2, Gold, SMT; Manufacturer: Samtec; CNHeader: FALSE; Current_A: 2.2A; Gender: Female; Voltage_V: 200V; Row_Count: 2; Pitch_mm: 0.8; Cert_UL: Y
R74-R79 = CMP-0025885-5: RES, 0, 5%, 0.1 W, 0603; Manufacturer: Yageo; Power_W: 100mW; TempCo: 200 ppm/C; Value_Code: 0000; Value: 0; EIA_Code: E24; SizeX_mm: 1.6; SizeZ_mm: 1; Value2: 0.1W; SizeArea_mm2: 1.28; AEC Qualified: N; VDC_V: 75V; AEC Category: Q200; SizeY_mm: 0.8; SizeAreaWB_mm2: 4.68
U12 U13 U16 U19 = CMP-0050159-1: Dual-Supply Hex-Buffer with Configurable Voltage Translation and Tri-State Outputs; Manufacturer: Texas Instruments; SizeZ_mm: 0.8mm; AEC Qualified: No; Data Rate: 380Mbits/s; Logic Function Desc: Non-Inverting; Number Of Inputs: 6; PositionCount: 1; Quiescent Current: 40uA; Standoff Height: 0mm; V A Max: 3.6V; V A Min: 1.2V
U14 U15 U17 U18 = CMP-0051710-3: Automotive Catalog Single Schmitt-Trigger Buffer, DCK0005A, LARGE T&R; Manufacturer: Texas Instruments; Generic Part Number: SN74LVC1G17-Q1; F @ Nom Voltage(Max)(Mhz): 150; Bits(#): 1; Schmitt Trigger: Yes; Sub-Family: Non-Inverting Buffer/Driver; Output Type: CMOS; Technology Family: LVC; Voltage(Nom)(V): 1.8,2.5,3.3,5; Logic: True; Input Type: CMOS/TTL; VCC(Min)(V): 1.65; Output Drive (IOL/IOH)(Max)(mA): 32/-32; VCC(Max)(V): 6.5; tpd @ Nom Voltage(Max)(ns): 14,9,8,7; ICC @ Nom Voltage(Max)(mA): 0.02; 3-State Output: No; AEC Category: Q200; AEC Qualified: Y; CompType: IC; SizeAreaWB_mm2: 9.3; SizeArea_mm2: 4.2; SizeX_mm: 2.1; SizeY_mm: 2.0; SizeZ_mm: 1.1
